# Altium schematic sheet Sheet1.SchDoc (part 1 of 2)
size A0
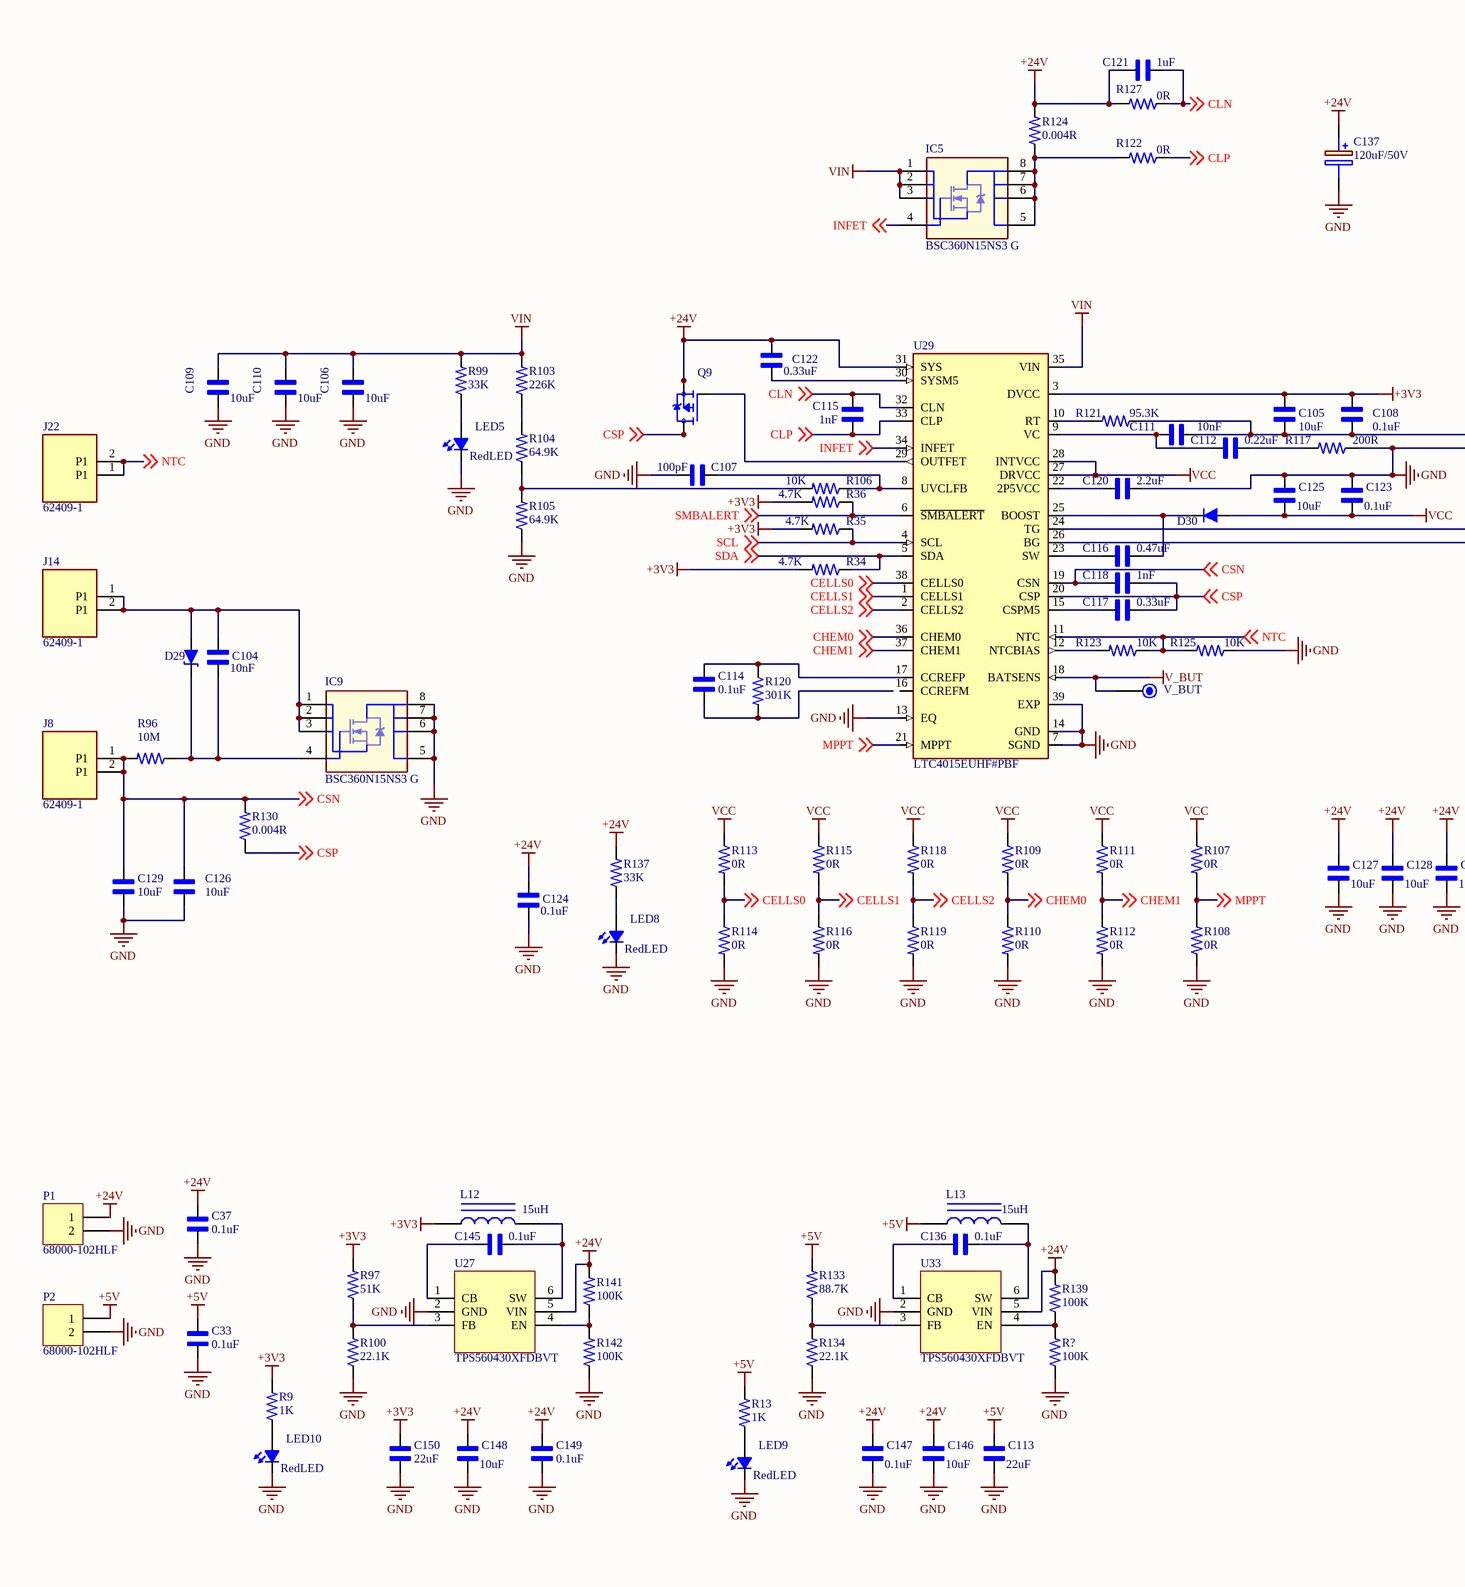
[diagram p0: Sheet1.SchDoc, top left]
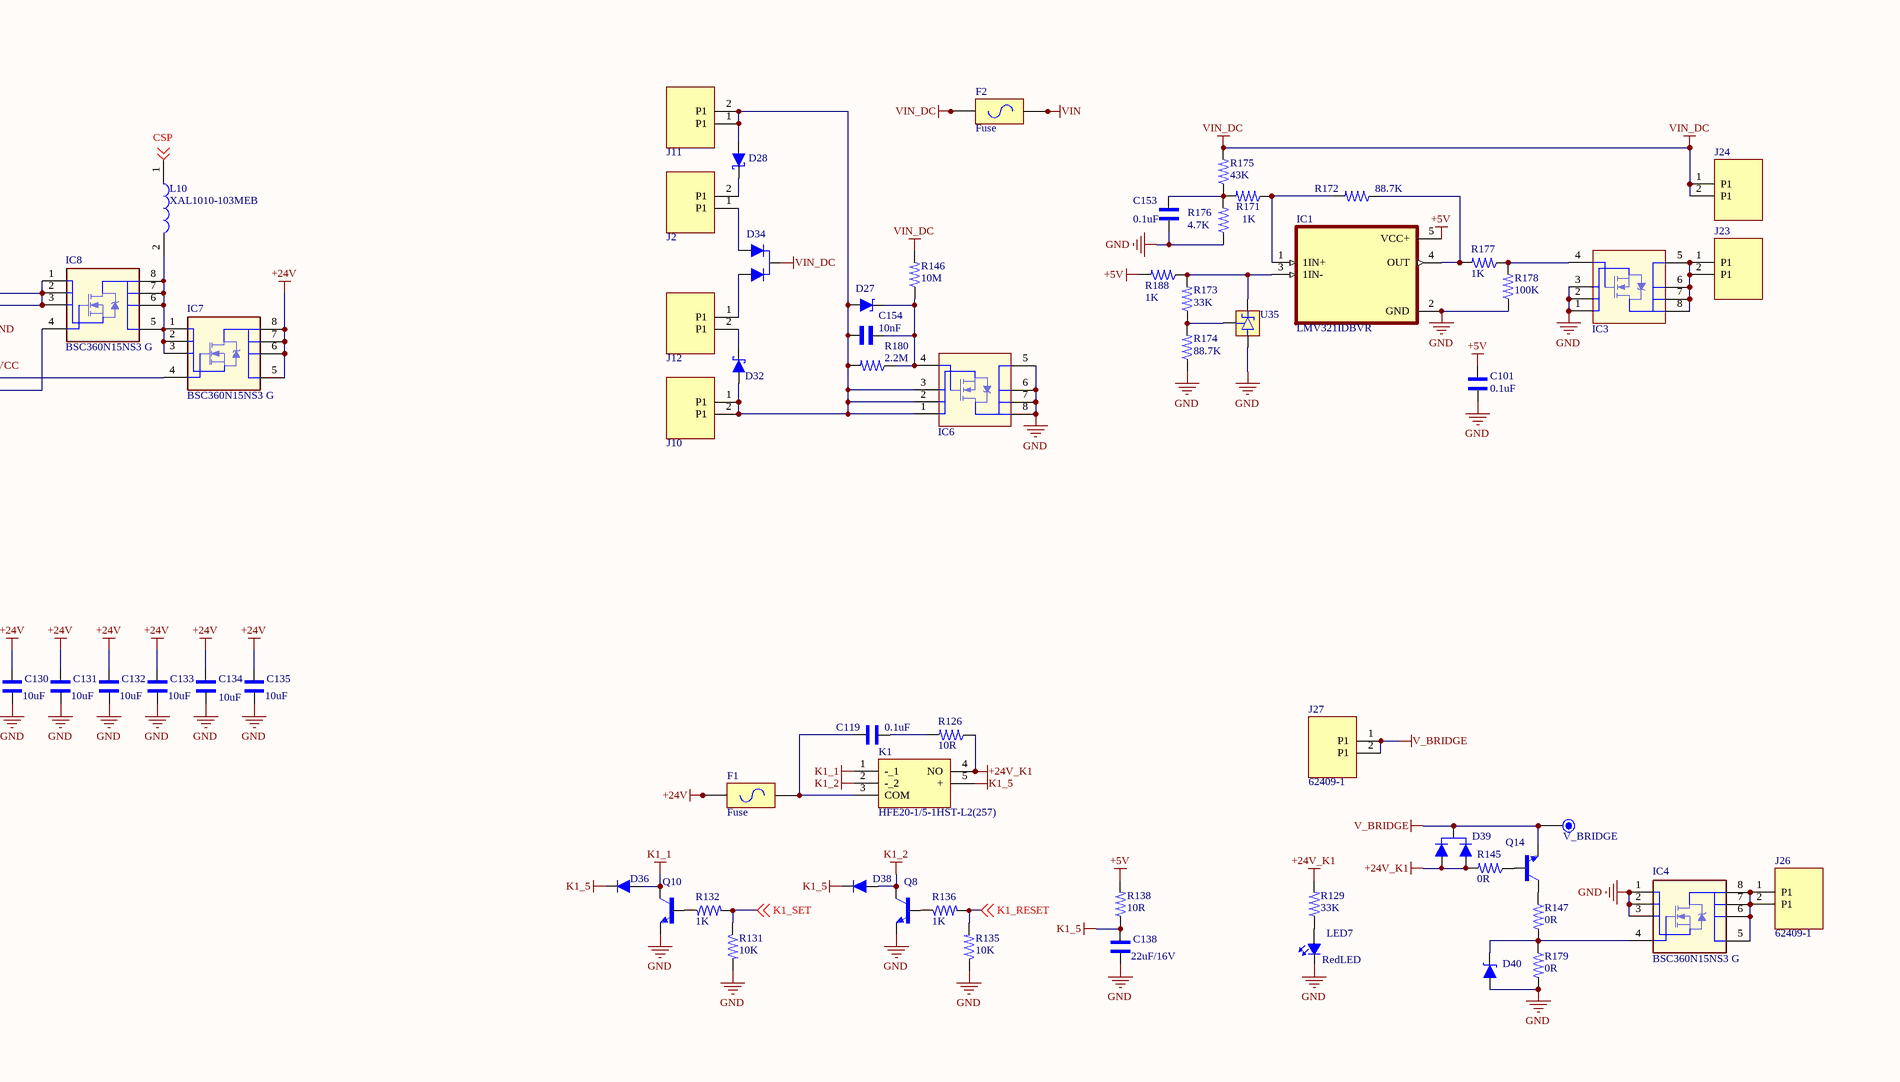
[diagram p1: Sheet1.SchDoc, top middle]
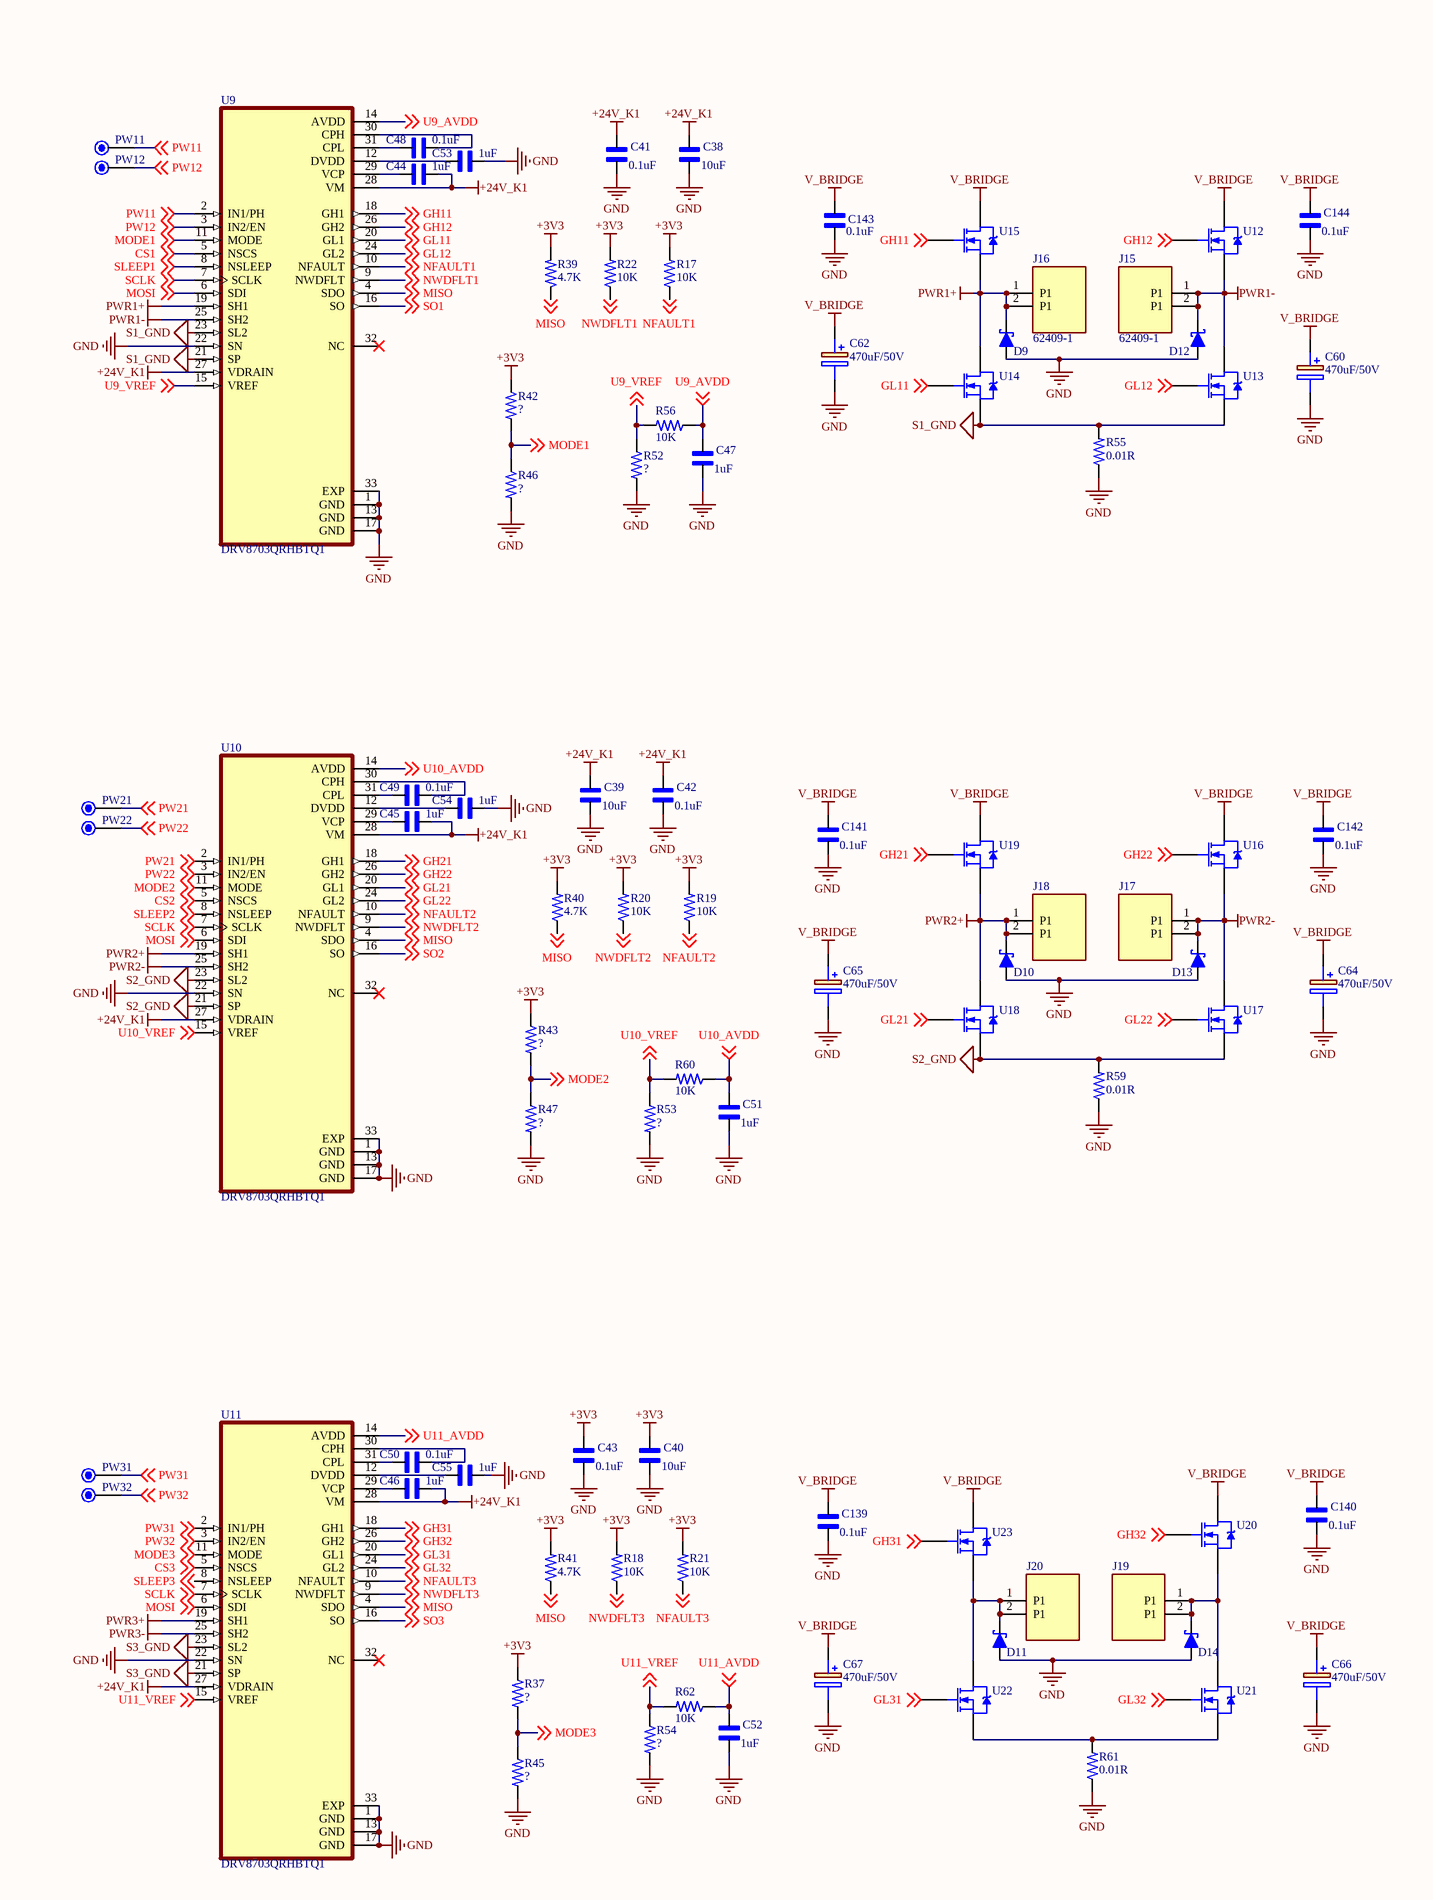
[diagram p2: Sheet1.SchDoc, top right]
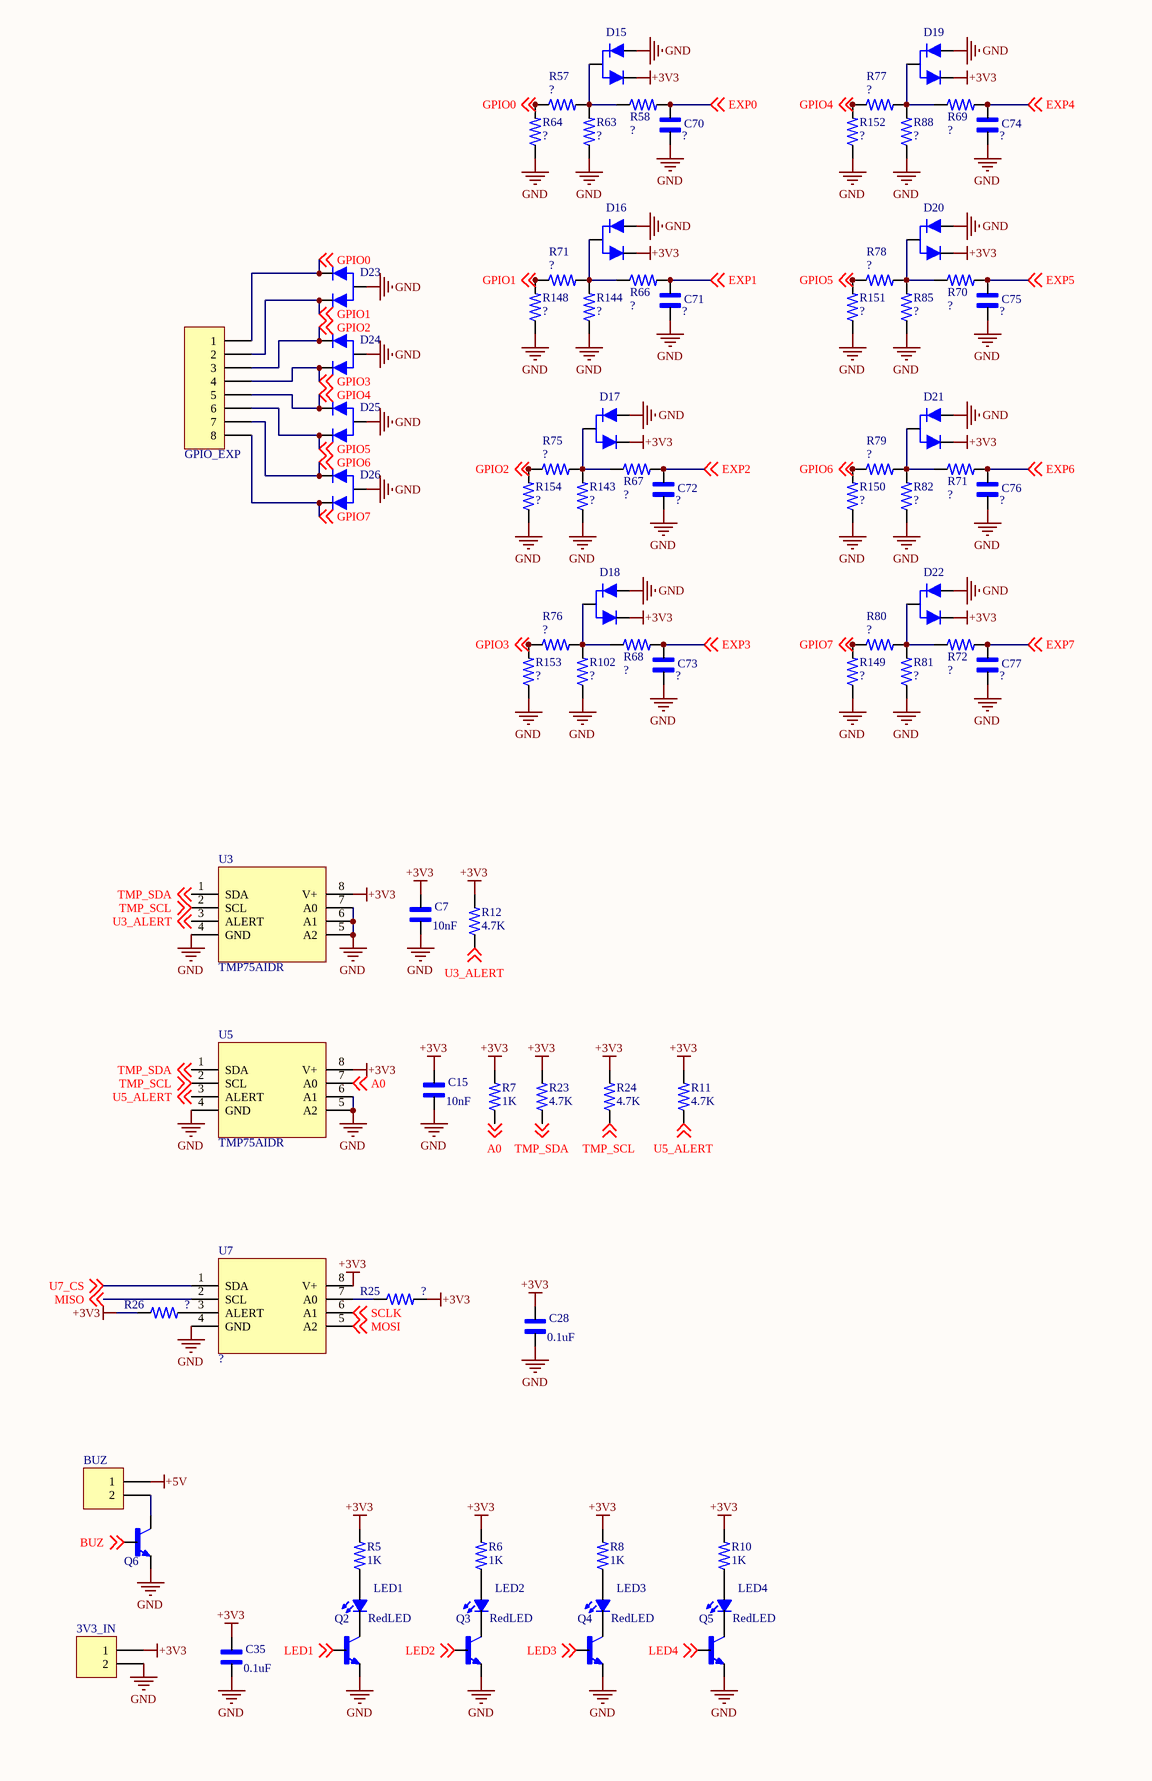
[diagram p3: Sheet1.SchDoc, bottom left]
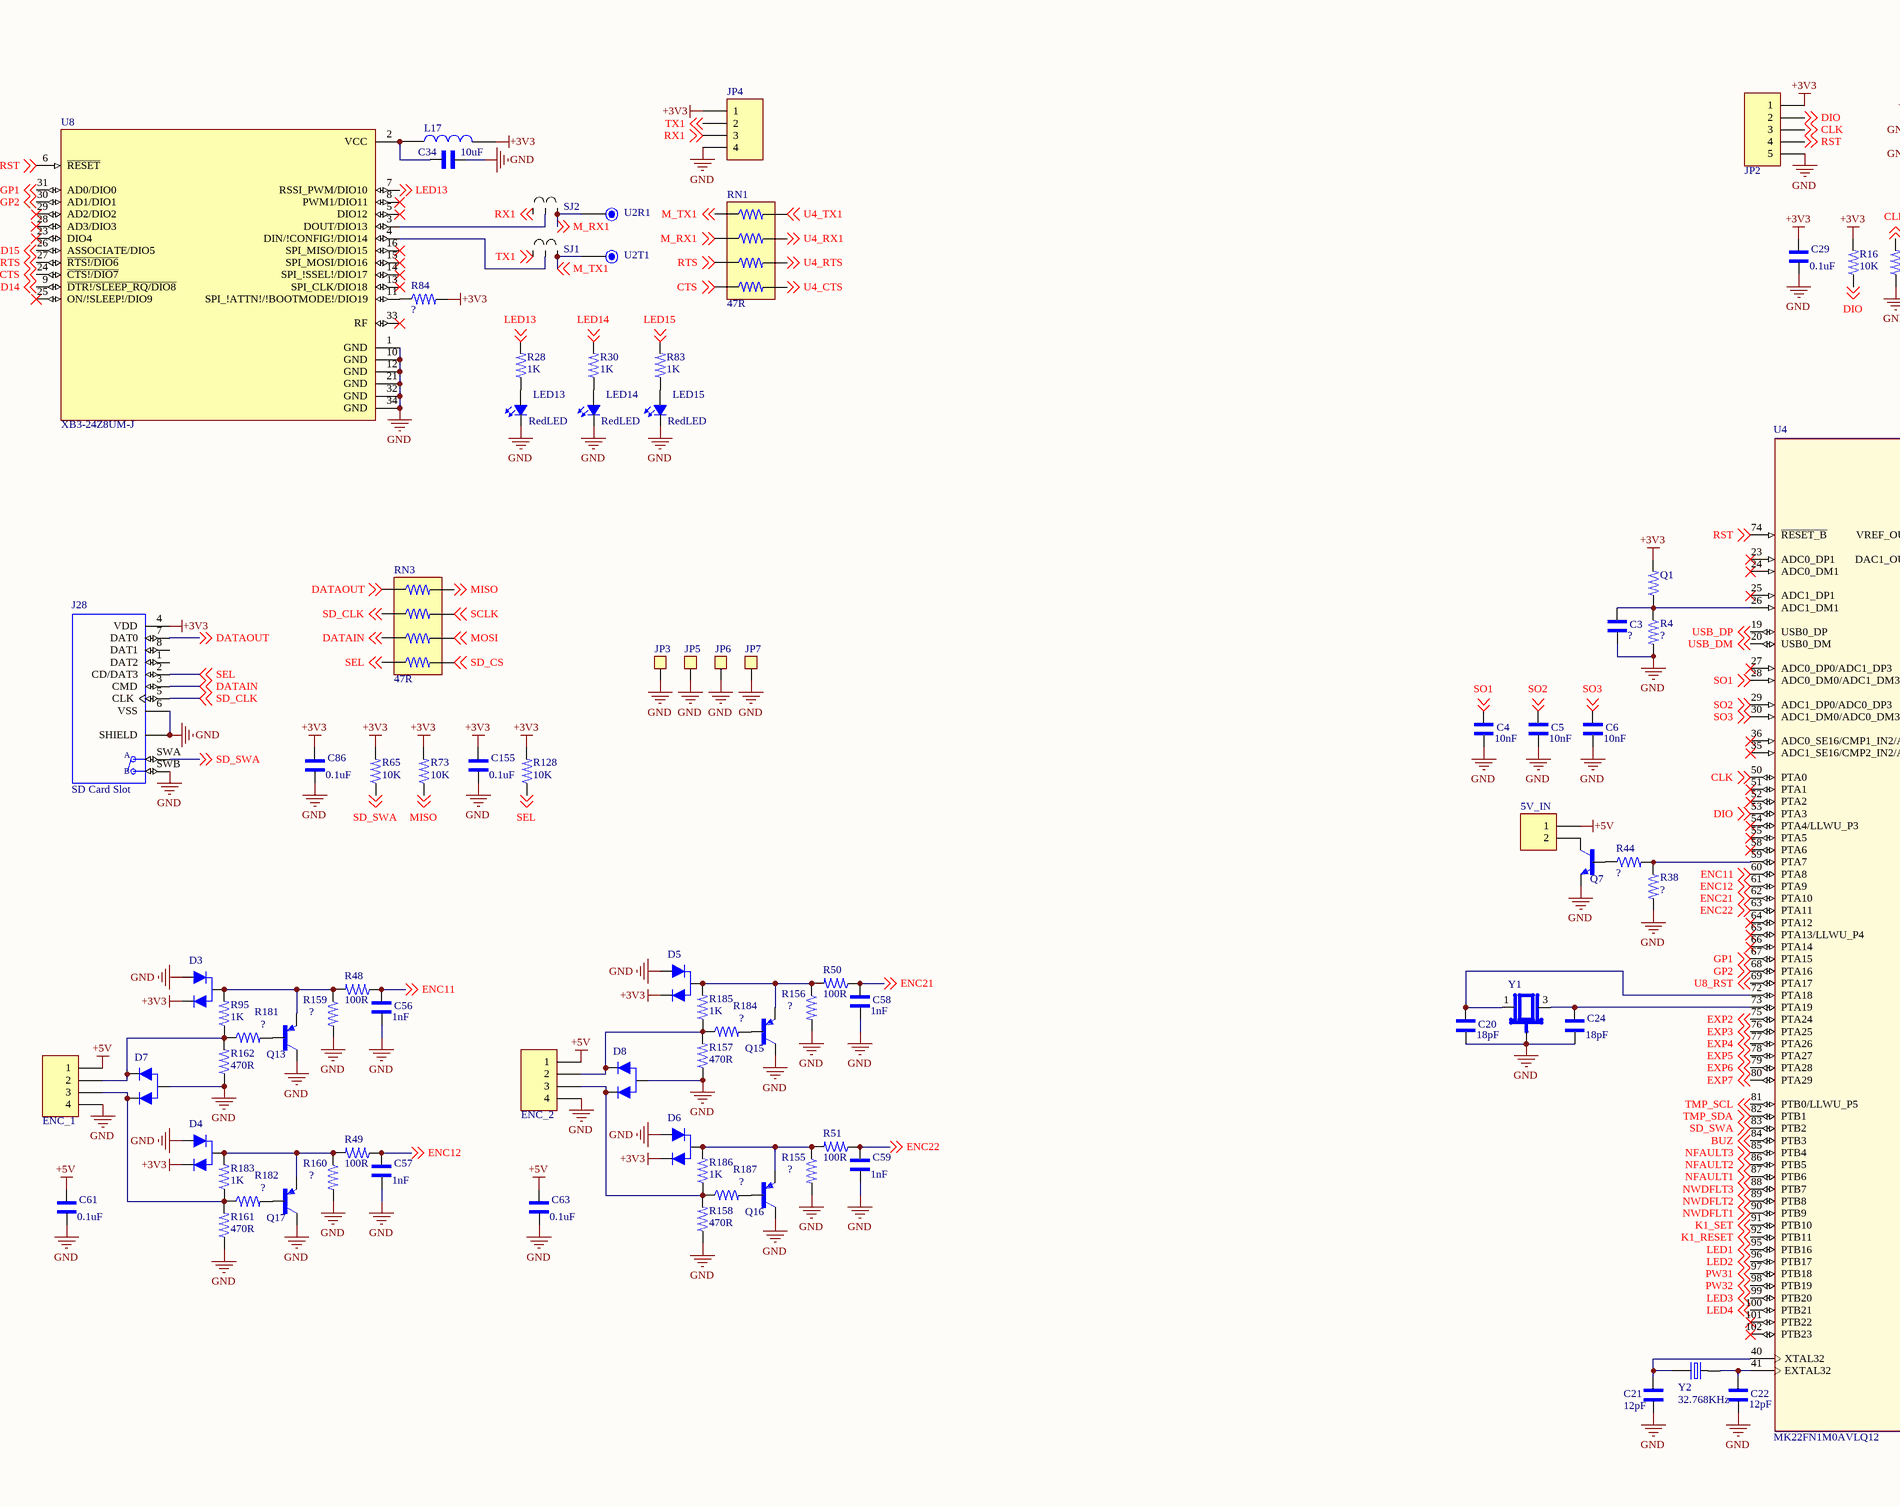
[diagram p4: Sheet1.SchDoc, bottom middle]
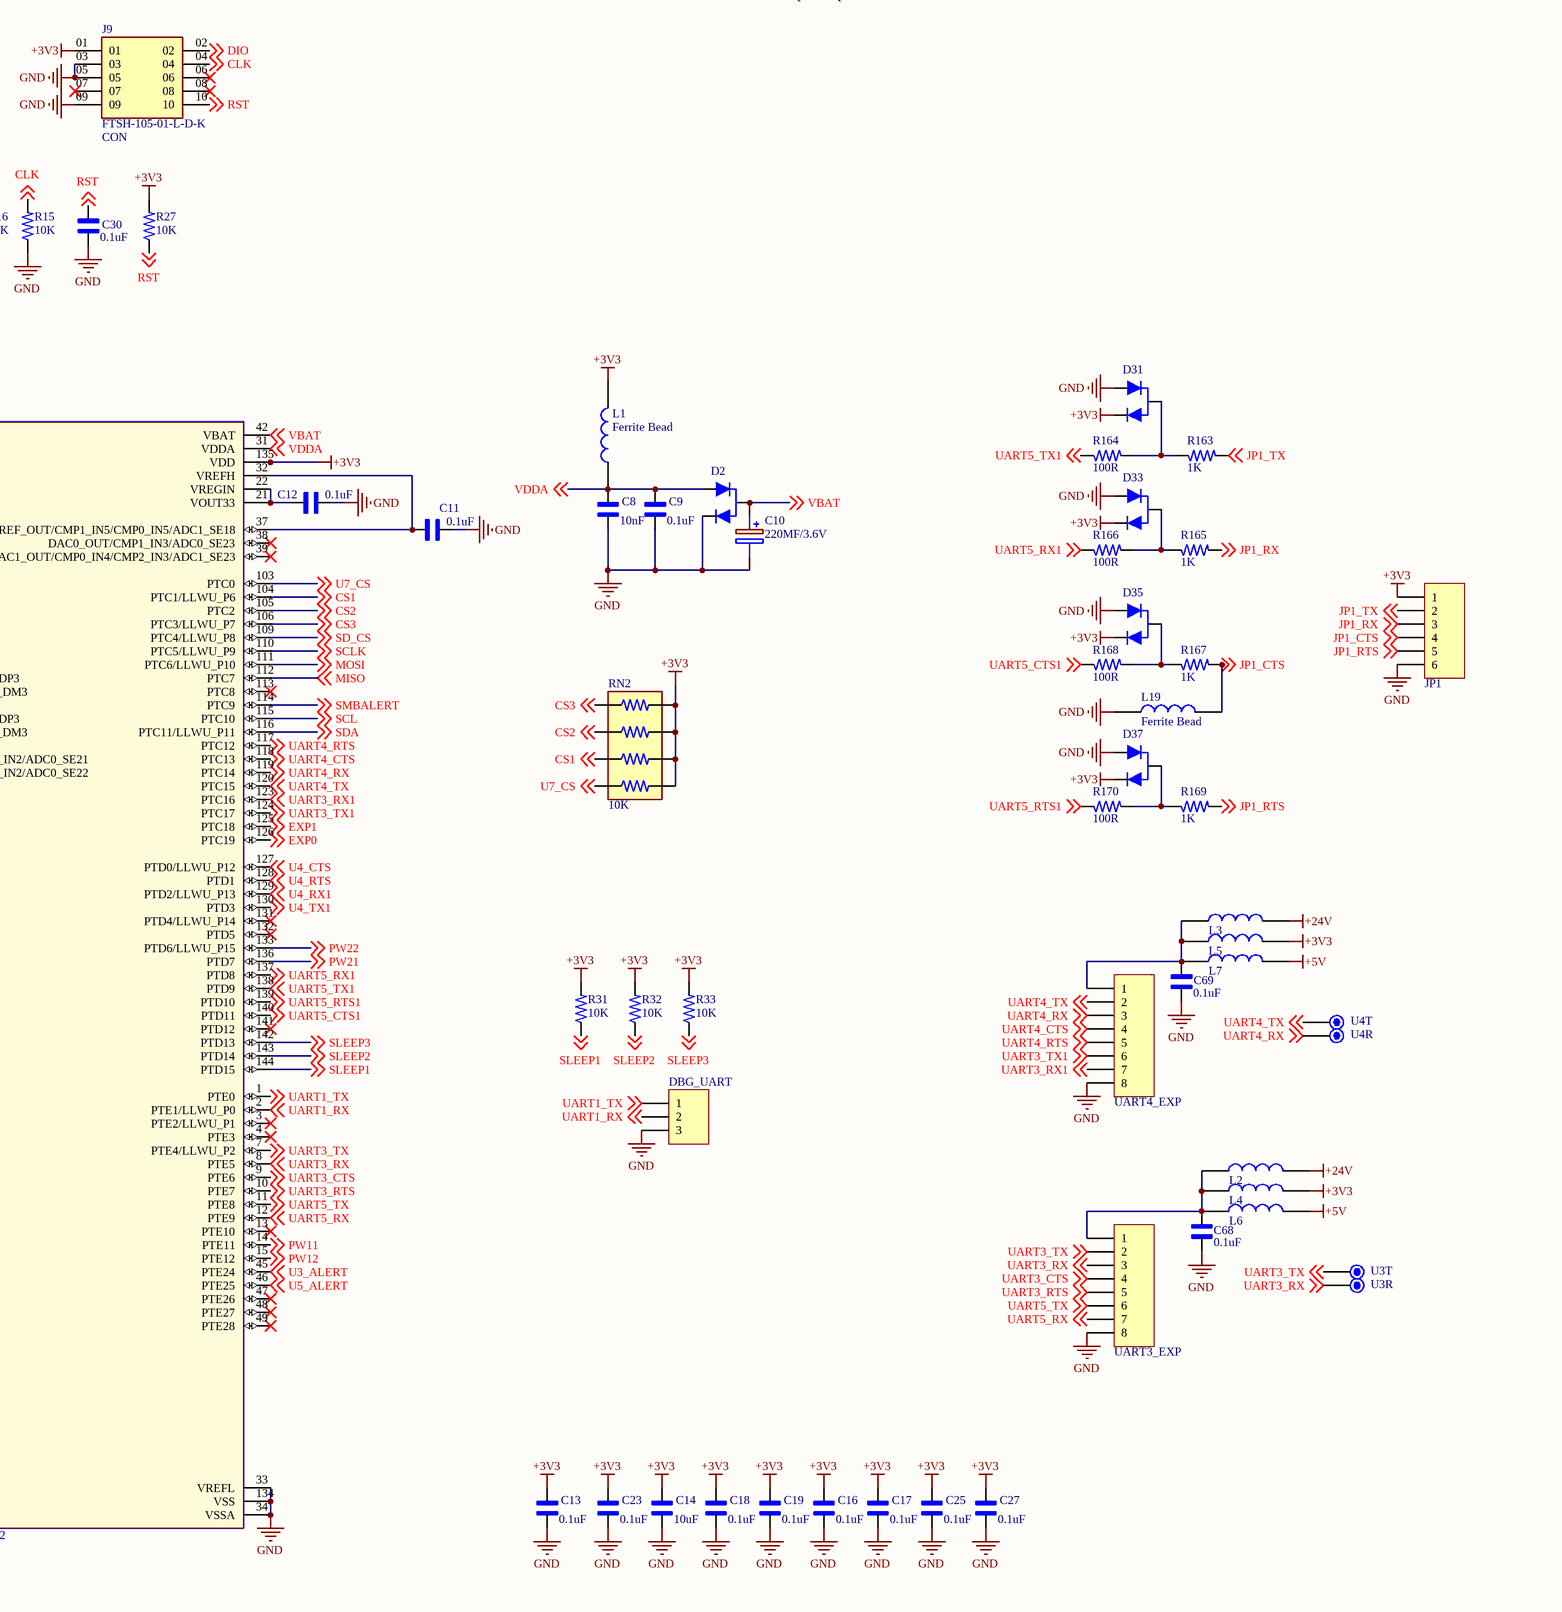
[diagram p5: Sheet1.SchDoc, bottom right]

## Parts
(Parts that share a designator on the sheet are numbered #1, #2 ... from top to bottom, then left to right.)
3V3_IN  68000-102HLF  [HDR1X2(male)]  (value not drawn)
5V_IN  68000-102HLF  [HDR1X2(male)]  (value not drawn)
BUZ  68000-102HLF  [HDR1X2(male)]  (value not drawn)
C3  C?  [CAPC_0805 (2012X140N)]  (value not drawn)
C4  value 10nF  [CAPC_0805 (2012X140N)]  (hidden comment: 08055C103KAT2A)
C5  value 10nF  [CAPC_0805 (2012X140N)]  (hidden comment: 08055C103KAT2A)
C6  value 10nF  [CAPC_0805 (2012X140N)]  (hidden comment: 08055C103KAT2A)
C7  value 10nF  [CAPC_0805 (2012X140N)]  (hidden comment: 08055C103KAT2A)
C8  value 10nF  [CAPC_0805 (2012X140N)]  (hidden comment: 08055C103KAT2A)
C9  value 0.1uF  [CAPC_0805 (2012X140N)]  (hidden comment: 0805B104K500CT)
C10  value 220MF/3.6V  [EEC-RG0V224H]  (hidden comment: EEC-RG0V224H)
C11  value 0.1uF  [CAPC_0805 (2012X140N)]  (hidden comment: 0805B104K500CT)
C12  value 0.1uF  [CAPC_0805 (2012X140N)]  (hidden comment: 0805B104K500CT)
C13  value 0.1uF  [CAPC_0805 (2012X140N)]  (hidden comment: 0805B104K500CT)
C14  value 10uF  [CAPC_0805 (2012X140N)]  (hidden comment: GRM21BR61E106KA73L)
C15  value 10nF  [CAPC_0805 (2012X140N)]  (hidden comment: 08055C103KAT2A)
C16  value 0.1uF  [CAPC_0805 (2012X140N)]  (hidden comment: 0805B104K500CT)
C17  value 0.1uF  [CAPC_0805 (2012X140N)]  (hidden comment: 0805B104K500CT)
C18  value 0.1uF  [CAPC_0805 (2012X140N)]  (hidden comment: 0805B104K500CT)
C19  value 0.1uF  [CAPC_0805 (2012X140N)]  (hidden comment: 0805B104K500CT)
C20  value 18pF  [CAPC_0805 (2012X140N)]  (hidden comment: 0805N180J500CT)
C21  value 12pF  [CAPC_0805 (2012X140N)]  (hidden comment: 0805N120J500CT)
C22  value 12pF  [CAPC_0805 (2012X140N)]  (hidden comment: 0805N120J500CT)
C23  value 0.1uF  [CAPC_0805 (2012X140N)]  (hidden comment: 0805B104K500CT)
C24  value 18pF  [CAPC_0805 (2012X140N)]  (hidden comment: 0805N180J500CT)
C25  value 0.1uF  [CAPC_0805 (2012X140N)]  (hidden comment: 0805B104K500CT)
C27  value 0.1uF  [CAPC_0805 (2012X140N)]  (hidden comment: 0805B104K500CT)
C28  value 0.1uF  [CAPC_0805 (2012X140N)]  (hidden comment: 0805B104K500CT)
C29  value 0.1uF  [CAPC_0805 (2012X140N)]  (hidden comment: 0805B104K500CT)
C30  value 0.1uF  [CAPC_0805 (2012X140N)]  (hidden comment: 0805B104K500CT)
C33  value 0.1uF  [CAPC_0805 (2012X140N)]  (hidden comment: 0805B104K500CT)
C34  value 10uF  [CAPC_0805 (2012X140N)]  (hidden comment: GRM21BR61E106KA73L)
C35  value 0.1uF  [CAPC_0805 (2012X140N)]  (hidden comment: 0805B104K500CT)
C37  value 0.1uF  [CAPC_0805 (2012X140N)]  (hidden comment: 0805B104K500CT)
C38  value 10uF  [CAPC_1210 (3225X280)]  (hidden comment: GRM32ER71H106KA12L)
C39  value 10uF  [CAPC_1210 (3225X280)]  (hidden comment: GRM32ER71H106KA12L)
C40  value 10uF  [CAPC_1210 (3225X280)]  (hidden comment: GRM32ER71H106KA12L)
C41  value 0.1uF  [CAPC_0805 (2012X140N)]  (hidden comment: 0805B104K500CT)
C42  value 0.1uF  [CAPC_0805 (2012X140N)]  (hidden comment: 0805B104K500CT)
C43  value 0.1uF  [CAPC_0805 (2012X140N)]  (hidden comment: 0805B104K500CT)
C44  value 1uF  [CAPC_0805 (2012X140N)]  (hidden comment: 08055C105KAT2A)
C45  value 1uF  [CAPC_0805 (2012X140N)]  (hidden comment: 08055C105KAT2A)
C46  value 1uF  [CAPC_0805 (2012X140N)]  (hidden comment: 08055C105KAT2A)
C47  value 1uF  [CAPC_0805 (2012X140N)]  (hidden comment: 08055C105KAT2A)
C48  value 0.1uF  [CAPC_0805 (2012X140N)]  (hidden comment: 0805B104K500CT)
C49  value 0.1uF  [CAPC_0805 (2012X140N)]  (hidden comment: 0805B104K500CT)
C50  value 0.1uF  [CAPC_0805 (2012X140N)]  (hidden comment: 0805B104K500CT)
C51  value 1uF  [CAPC_0805 (2012X140N)]  (hidden comment: 08055C105KAT2A)
C52  value 1uF  [CAPC_0805 (2012X140N)]  (hidden comment: 08055C105KAT2A)
C53  value 1uF  [CAPC_0805 (2012X140N)]  (hidden comment: 08055C105KAT2A)
C54  value 1uF  [CAPC_0805 (2012X140N)]  (hidden comment: 08055C105KAT2A)
C55  value 1uF  [CAPC_0805 (2012X140N)]  (hidden comment: 08055C105KAT2A)
C56  value 1nF  [CAPC_0805 (2012X140N)]  (hidden comment: 08055C102KAT4A)
C57  value 1nF  [CAPC_0805 (2012X140N)]  (hidden comment: 08055C102KAT4A)
C58  value 1nF  [CAPC_0805 (2012X140N)]  (hidden comment: 08055C102KAT4A)
C59  value 1nF  [CAPC_0805 (2012X140N)]  (hidden comment: 08055C102KAT4A)
C60  value 470uF/50V  [CAPPRD(5x10)]  (hidden comment: ESH477M050AH4AA)
C61  value 0.1uF  [CAPC_0805 (2012X140N)]  (hidden comment: 0805B104K500CT)
C62  value 470uF/50V  [CAPPRD(5x10)]  (hidden comment: ESH477M050AH4AA)
C63  value 0.1uF  [CAPC_0805 (2012X140N)]  (hidden comment: 0805B104K500CT)
C64  value 470uF/50V  [CAPPRD(5x10)]  (hidden comment: ESH477M050AH4AA)
C65  value 470uF/50V  [CAPPRD(5x10)]  (hidden comment: ESH477M050AH4AA)
C66  value 470uF/50V  [CAPPRD(5x10)]  (hidden comment: ESH477M050AH4AA)
C67  value 470uF/50V  [CAPPRD(5x10)]  (hidden comment: ESH477M050AH4AA)
C68  value 0.1uF  [CAPC_0805 (2012X140N)]  (hidden comment: 0805B104K500CT)
C69  value 0.1uF  [CAPC_0805 (2012X140N)]  (hidden comment: 0805B104K500CT)
C70  C?  [CAPC_0805 (2012X140N)]  (value not drawn)
C71  C?  [CAPC_0805 (2012X140N)]  (value not drawn)
C72  C?  [CAPC_0805 (2012X140N)]  (value not drawn)
C73  C?  [CAPC_0805 (2012X140N)]  (value not drawn)
C74  C?  [CAPC_0805 (2012X140N)]  (value not drawn)
C75  C?  [CAPC_0805 (2012X140N)]  (value not drawn)
C76  C?  [CAPC_0805 (2012X140N)]  (value not drawn)
C77  C?  [CAPC_0805 (2012X140N)]  (value not drawn)
C86  value 0.1uF  [CAPC_0805 (2012X140N)]  (hidden comment: 0805B104K500CT)
C101  value 0.1uF  [CAPC_0805 (2012X140N)]  (hidden comment: 0805B104K500CT)
C104  value 10nF  [CAPC_0805 (2012X140N)]  (hidden comment: 08055C103KAT2A)
C105  value 10uF  [CAPC_0805 (2012X140N)]  (hidden comment: GRM21BR61E106KA73L)
C106  value 10uF  [CAPC_1210 (3225X280)]  (hidden comment: GRM32ER71H106KA12L)
C107  value 100pF  [CAPC_0805 (2012X140N)]  (hidden comment: VJ0805A101JXAAC)
C108  value 0.1uF  [CAPC_0805 (2012X140N)]  (hidden comment: 0805B104K500CT)
C109  value 10uF  [CAPC_1210 (3225X280)]  (hidden comment: GRM32ER71H106KA12L)
C110  value 10uF  [CAPC_1210 (3225X280)]  (hidden comment: GRM32ER71H106KA12L)
C111  value 10nF  [CAPC_0805 (2012X140N)]  (hidden comment: 08055C103KAT2A)
C112  value 0.22uF  [CAPC_0805 (2012X140N)]  (hidden comment: UMK212B7224KG-T)
C113  value 22uF  [CAPC_0805 (2012X140N)]  (hidden comment: GRM21BR60J226ME39L)
C114  value 0.1uF  [CAPC_0805 (2012X140N)]  (hidden comment: 0805B104K500CT)
C115  value 1nF  [CAPC_0805 (2012X140N)]  (hidden comment: 08055C102KAT4A)
C116  value 0.47uF  [CAPC_0805 (2012X140N)]  (hidden comment: CC0805ZRY5V9BB474)
C117  value 0.33uF  [CAPC_0805 (2012X140N)]  (hidden comment: VJ0805V334MXACW1BC)
C118  value 1nF  [CAPC_0805 (2012X140N)]  (hidden comment: 08055C102KAT4A)
C119  value 0.1uF  [CAP_1206 (C3216X88N)]  (hidden comment: C1206C104M5RACTU)
C120  value 2.2uF  [CAPC_0805 (2012X140N)]  (hidden comment: UMK212BB7225KG-T)
C121  value 1uF  [CAPC_0805 (2012X140N)]  (hidden comment: 08055C105KAT2A)
C122  value 0.33uF  [CAPC_0805 (2012X140N)]  (hidden comment: VJ0805V334MXACW1BC)
C123  value 0.1uF  [CAPC_0805 (2012X140N)]  (hidden comment: 0805B104K500CT)
C124  value 0.1uF  [CAPC_0805 (2012X140N)]  (hidden comment: 0805B104K500CT)
C125  value 10uF  [CAPC_0805 (2012X140N)]  (hidden comment: GRM21BR61E106KA73L)
C126  value 10uF  [CAPC_1210 (3225X280)]  (hidden comment: GRM32ER71H106KA12L)
C127  value 10uF  [CAPC_1210 (3225X280)]  (hidden comment: GRM32ER71H106KA12L)
C128  value 10uF  [CAPC_1210 (3225X280)]  (hidden comment: GRM32ER71H106KA12L)
C129  value 10uF  [CAPC_1210 (3225X280)]  (hidden comment: GRM32ER71H106KA12L)
C130  value 10uF  [CAPC_1210 (3225X280)]  (hidden comment: GRM32ER71H106KA12L)
C131  value 10uF  [CAPC_1210 (3225X280)]  (hidden comment: GRM32ER71H106KA12L)
C132  value 10uF  [CAPC_1210 (3225X280)]  (hidden comment: GRM32ER71H106KA12L)
C133  value 10uF  [CAPC_1210 (3225X280)]  (hidden comment: GRM32ER71H106KA12L)
C134  value 10uF  [CAPC_1210 (3225X280)]  (hidden comment: GRM32ER71H106KA12L)
C135  value 10uF  [CAPC_1210 (3225X280)]  (hidden comment: GRM32ER71H106KA12L)
C136  value 0.1uF  [CAPC_0805 (2012X140N)]  (hidden comment: 0805B104K500CT)
C137  value 120uF/50V  [CAPPRD(5x10)]  (hidden comment: 860020675017)
C138  value 22uF/16V  [CAP_1206 (C3216X88N)]  (hidden comment: 1206X226K160CT)
C139  value 0.1uF  [CAPC_0805 (2012X140N)]  (hidden comment: 0805B104K500CT)
C140  value 0.1uF  [CAPC_0805 (2012X140N)]  (hidden comment: 0805B104K500CT)
C141  value 0.1uF  [CAPC_0805 (2012X140N)]  (hidden comment: 0805B104K500CT)
C142  value 0.1uF  [CAPC_0805 (2012X140N)]  (hidden comment: 0805B104K500CT)
C143  value 0.1uF  [CAPC_0805 (2012X140N)]  (hidden comment: 0805B104K500CT)
C144  value 0.1uF  [CAPC_0805 (2012X140N)]  (hidden comment: 0805B104K500CT)
C145  value 0.1uF  [CAPC_0805 (2012X140N)]  (hidden comment: 0805B104K500CT)
C146  value 10uF  [CAPC_1210 (3225X280)]  (hidden comment: GRM32ER71H106KA12L)
C147  value 0.1uF  [CAPC_0805 (2012X140N)]  (hidden comment: 0805B104K500CT)
C148  value 10uF  [CAPC_1210 (3225X280)]  (hidden comment: GRM32ER71H106KA12L)
C149  value 0.1uF  [CAPC_0805 (2012X140N)]  (hidden comment: 0805B104K500CT)
C150  value 22uF  [CAPC_0805 (2012X140N)]  (hidden comment: GRM21BR60J226ME39L)
C153  value 0.1uF  [CAPC_0805 (2012X140N)]  (hidden comment: 0805B104K500CT)
C154  value 10nF  [CAPC_0805 (2012X140N)]  (hidden comment: 08055C103KAT2A)
C155  value 0.1uF  [CAPC_0805 (2012X140N)]  (hidden comment: 0805B104K500CT)
D2  BAS40-04E6327  [SOT-23-3(TO-236)]  (value not drawn)
D3  BAT54S,215  [SOT-23-3(TO-236)]  (value not drawn)
D4  BAT54S,215  [SOT-23-3(TO-236)]  (value not drawn)
D5  BAT54S,215  [SOT-23-3(TO-236)]  (value not drawn)
D6  BAT54S,215  [SOT-23-3(TO-236)]  (value not drawn)
D7  BAS40-06  [SOT-23-3(TO-236)]  (value not drawn)
D8  BAS40-06  [SOT-23-3(TO-236)]  (value not drawn)
D9  SMLJ43CA  [DO-214]  (value not drawn)
D10  SMLJ43CA  [DO-214]  (value not drawn)
D11  SMLJ43CA  [DO-214]  (value not drawn)
D12  SMLJ43CA  [DO-214]  (value not drawn)
D13  SMLJ43CA  [DO-214]  (value not drawn)
D14  SMLJ43CA  [DO-214]  (value not drawn)
D15  BAT54S,215  [SOT-23-3(TO-236)]  (value not drawn)
D16  BAT54S,215  [SOT-23-3(TO-236)]  (value not drawn)
D17  BAT54S,215  [SOT-23-3(TO-236)]  (value not drawn)
D18  BAT54S,215  [SOT-23-3(TO-236)]  (value not drawn)
D19  BAT54S,215  [SOT-23-3(TO-236)]  (value not drawn)
D20  BAT54S,215  [SOT-23-3(TO-236)]  (value not drawn)
D21  BAT54S,215  [SOT-23-3(TO-236)]  (value not drawn)
D22  BAT54S,215  [SOT-23-3(TO-236)]  (value not drawn)
D23  BAS40-06  [SOT-23-3(TO-236)]  (value not drawn)
D24  BAS40-06  [SOT-23-3(TO-236)]  (value not drawn)
D25  BAS40-06  [SOT-23-3(TO-236)]  (value not drawn)
D26  BAS40-06  [SOT-23-3(TO-236)]  (value not drawn)
D27  BZX384-B15,115  [SOD323 (SOD2513X114N)]  (value not drawn)
D28  SMAJ43A-E3/61  [DO-214]  (value not drawn)
D29  BZX384-B15,115  [SOD323 (SOD2513X114N)]  (value not drawn)
D30  1N4148WS-7-F  [SOD323 (SOD2513X114N)]  (value not drawn)
D31  BAT54S,215  [SOT-23-3(TO-236)]  (value not drawn)
D32  SMAJ43A-E3/61  [DO-214]  (value not drawn)
D33  BAT54S,215  [SOT-23-3(TO-236)]  (value not drawn)
D34  MBRD20100CT-13  [TO-252AA(DPAK229P990X238-3N)]  (value not drawn)
D35  BAT54S,215  [SOT-23-3(TO-236)]  (value not drawn)
D36  1N4148WS-7-F  [SOD323 (SOD2513X114N)]  (value not drawn)
D37  BAT54S,215  [SOT-23-3(TO-236)]  (value not drawn)
D38  1N4148WS-7-F  [SOD323 (SOD2513X114N)]  (value not drawn)
D39  MBRD20100CT-13  [TO-252AA(DPAK229P990X238-3N)]  (value not drawn)
D40  BZX384-B15,115  [SOD323 (SOD2513X114N)]  (value not drawn)
DBG_UART  68000-103HLF  [HDR1X3 (male)]  (value not drawn)
ENC_1  68000-104HLF  [HDR1X4(male)]  (value not drawn)
ENC_2  68000-104HLF  [HDR1X4(male)]  (value not drawn)
F1  value Fuse  [FUSE Holder]  (hidden comment: C3130)
F2  value Fuse  [FUSE Holder]  (hidden comment: C3130)
GPIO_EXP  68001-108HLF  [HDR1X8 (male)]  (value not drawn)
IC1  LMV321IDBVR  [SOT23-5 (95P284X120-5N)]
IC3  BSC360N15NS3 G  [TRANS_BSC022N04LS6ATMA1]  (value not drawn)
IC4  BSC360N15NS3 G  [TRANS_BSC022N04LS6ATMA1]
IC5  BSC360N15NS3 G  [TRANS_BSC022N04LS6ATMA1]
IC6  BSC360N15NS3 G  [TRANS_BSC022N04LS6ATMA1]  (value not drawn)
IC7  BSC360N15NS3 G  [TRANS_BSC022N04LS6ATMA1]
IC8  BSC360N15NS3 G  [TRANS_BSC022N04LS6ATMA1]
IC9  BSC360N15NS3 G  [TRANS_BSC022N04LS6ATMA1]
J2  62409-1  [TE_62409-1]  (value not drawn)
J8  62409-1  [TE_62409-1]
J9  FTSH-105-01-L-D-K  value CON  [FTSH-105-01-L-D-K]
J10  62409-1  [TE_62409-1]  (value not drawn)
J11  62409-1  [TE_62409-1]  (value not drawn)
J12  62409-1  [TE_62409-1]  (value not drawn)
J14  62409-1  [TE_62409-1]
J15  62409-1  [TE_62409-1]
J16  62409-1  [TE_62409-1]
J17  62409-1  [TE_62409-1]  (value not drawn)
J18  62409-1  [TE_62409-1]  (value not drawn)
J19  62409-1  [TE_62409-1]  (value not drawn)
J20  62409-1  [TE_62409-1]  (value not drawn)
J22  62409-1  [TE_62409-1]
J23  62409-1  [TE_62409-1]  (value not drawn)
J24  62409-1  [TE_62409-1]  (value not drawn)
J26  62409-1  [TE_62409-1]
J27  62409-1  [TE_62409-1]
J28  value SD Card Slot  [HRS_DM3AT-SF-PEJM5]  (hidden comment: DM3AT-SF-PEJM5)
JP1  68000-106HLF  [HDR1X6(male)]  (value not drawn)
JP2  68000-105HLF  [HDR1X5(male)]  (value not drawn)
JP3  PH1-01-UA  [HDR1(male)]  (value not drawn)
JP4  68000-104HLF  [HDR1X4(male)]  (value not drawn)
JP5  PH1-01-UA  [HDR1(male)]  (value not drawn)
JP6  PH1-01-UA  [HDR1(male)]  (value not drawn)
JP7  PH1-01-UA  [HDR1(male)]  (value not drawn)
K1  HFE20-1/5-1HST-L2(257)  [HFE20151HSTL2257]
L1  value Ferrite Bead  [RESC_0805 (2012X50N)]  (hidden comment: BK2125HS601-T)
L2  BK2125HS601-T  [RESC_0805 (2012X50N)]  (value not drawn)
L3  BK2125HS601-T  [RESC_0805 (2012X50N)]  (value not drawn)
L4  BK2125HS601-T  [RESC_0805 (2012X50N)]  (value not drawn)
L5  BK2125HS601-T  [RESC_0805 (2012X50N)]  (value not drawn)
L6  BK2125HS601-T  [RESC_0805 (2012X50N)]  (value not drawn)
L7  BK2125HS601-T  [RESC_0805 (2012X50N)]  (value not drawn)
L10  XAL1010-103MEB  [XAL1010103MEB]
L12  value 15uH  [INDPM6965X300N]  (hidden comment: SRN6045-150M)
L13  value 15uH  [INDPM6965X300N]  (hidden comment: SRN6045-150M)
L17  BK2125HS601-T  [RESC_0805 (2012X50N)]  (value not drawn)
L19  value Ferrite Bead  [RESC_0805 (2012X50N)]  (hidden comment: BK2125HS601-T)
LED1  value RedLED  [LED_0805_R]  (hidden comment: EL-17-21SURC/S530-A2/TR8)
LED2  value RedLED  [LED_0805_R]  (hidden comment: EL-17-21SURC/S530-A2/TR8)
LED3  value RedLED  [LED_0805_R]  (hidden comment: EL-17-21SURC/S530-A2/TR8)
LED4  value RedLED  [LED_0805_R]  (hidden comment: EL-17-21SURC/S530-A2/TR8)
LED5  value RedLED  [LED_0805_R]  (hidden comment: EL-17-21SURC/S530-A2/TR8)
LED7  value RedLED  [LED_0805_R]  (hidden comment: EL-17-21SURC/S530-A2/TR8)
LED8  value RedLED  [LED_0805_R]  (hidden comment: EL-17-21SURC/S530-A2/TR8)
LED9  value RedLED  [LED_0805_R]  (hidden comment: EL-17-21SURC/S530-A2/TR8)
LED10  value RedLED  [LED_0805_R]  (hidden comment: EL-17-21SURC/S530-A2/TR8)
LED13  value RedLED  [LED_0805_R]  (hidden comment: EL-17-21SURC/S530-A2/TR8)
LED14  value RedLED  [LED_0805_R]  (hidden comment: EL-17-21SURC/S530-A2/TR8)
LED15  value RedLED  [LED_0805_R]  (hidden comment: EL-17-21SURC/S530-A2/TR8)
P1  68000-102HLF  [HDR1X2(male)]
P2  68000-102HLF  [HDR1X2(male)]
PW11  E_PAD  [E_PAD (SMD)]  (value not drawn)
PW12  E_PAD  [E_PAD (SMD)]  (value not drawn)
PW21  E_PAD  [E_PAD (SMD)]  (value not drawn)
PW22  E_PAD  [E_PAD (SMD)]  (value not drawn)
PW31  E_PAD  [E_PAD (SMD)]  (value not drawn)
PW32  E_PAD  [E_PAD (SMD)]  (value not drawn)
Q1  Q?  [RES (0603)]  (value not drawn)
Q2  PDTC114ET,215  [SOT-23-3(TO-236)]  (value not drawn)
Q3  PDTC114ET,215  [SOT-23-3(TO-236)]  (value not drawn)
Q4  PDTC114ET,215  [SOT-23-3(TO-236)]  (value not drawn)
Q5  PDTC114ET,215  [SOT-23-3(TO-236)]  (value not drawn)
Q6  PDTC114ET,215  [SOT-23-3(TO-236)]  (value not drawn)
Q7  PDTC114ET,215  [SOT-23-3(TO-236)]  (value not drawn)
Q8  BC847B-7-F  [SOT-23-3(TO-236)]  (value not drawn)
Q9  SI7611DN-T1-GE3  [SIS468DN-T1-GE3]  (value not drawn)
Q10  BC847B-7-F  [SOT-23-3(TO-236)]  (value not drawn)
Q13  PNP TRANS  [SOT-23-3(TO-236)]  (value not drawn)
Q14  BC847B-7-F  [SOT-23-3(TO-236)]  (value not drawn)
Q15  PNP TRANS  [SOT-23-3(TO-236)]  (value not drawn)
Q16  PNP TRANS  [SOT-23-3(TO-236)]  (value not drawn)
Q17  PNP TRANS  [SOT-23-3(TO-236)]  (value not drawn)
R4  R?  [RESC_0805 (2012X50N)]  (value not drawn)
R5  value 1K  [RESC_0805 (2012X50N)]  (hidden comment: RC0805FR-071KL)
R6  value 1K  [RESC_0805 (2012X50N)]  (hidden comment: RC0805FR-071KL)
R7  value 1K  [RESC_0805 (2012X50N)]  (hidden comment: RC0805FR-071KL)
R8  value 1K  [RESC_0805 (2012X50N)]  (hidden comment: RC0805FR-071KL)
R9  value 1K  [RESC_0805 (2012X50N)]  (hidden comment: RC0805FR-071KL)
R10  value 1K  [RESC_0805 (2012X50N)]  (hidden comment: RC0805FR-071KL)
R11  value 4.7K  [RESC_0805 (2012X50N)]  (hidden comment: CRCW08054K70FKEA)
R12  value 4.7K  [RESC_0805 (2012X50N)]  (hidden comment: CRCW08054K70FKEA)
R13  value 1K  [RESC_0805 (2012X50N)]  (hidden comment: RC0805FR-071KL)
R15  value 10K  [RESC_0805 (2012X50N)]  (hidden comment: RC0805FR-0710KL)
R16  value 10K  [RESC_0805 (2012X50N)]  (hidden comment: RC0805FR-0710KL)
R17  value 10K  [RESC_0805 (2012X50N)]  (hidden comment: RC0805FR-0710KL)
R18  value 10K  [RESC_0805 (2012X50N)]  (hidden comment: RC0805FR-0710KL)
R19  value 10K  [RESC_0805 (2012X50N)]  (hidden comment: RC0805FR-0710KL)
R20  value 10K  [RESC_0805 (2012X50N)]  (hidden comment: RC0805FR-0710KL)
R21  value 10K  [RESC_0805 (2012X50N)]  (hidden comment: RC0805FR-0710KL)
R22  value 10K  [RESC_0805 (2012X50N)]  (hidden comment: RC0805FR-0710KL)
R23  value 4.7K  [RESC_0805 (2012X50N)]  (hidden comment: CRCW08054K70FKEA)
R24  value 4.7K  [RESC_0805 (2012X50N)]  (hidden comment: CRCW08054K70FKEA)
R25  R?  [RESC_0805 (2012X50N)]  (value not drawn)
R26  R?  [RESC_0805 (2012X50N)]  (value not drawn)
R27  value 10K  [RESC_0805 (2012X50N)]  (hidden comment: RC0805FR-0710KL)
R28  value 1K  [RESC_0805 (2012X50N)]  (hidden comment: RC0805FR-071KL)
R30  value 1K  [RESC_0805 (2012X50N)]  (hidden comment: RC0805FR-071KL)
R31  value 10K  [RESC_0805 (2012X50N)]  (hidden comment: RC0805FR-0710KL)
R32  value 10K  [RESC_0805 (2012X50N)]  (hidden comment: RC0805FR-0710KL)
R33  value 10K  [RESC_0805 (2012X50N)]  (hidden comment: RC0805FR-0710KL)
R34  value 4.7K  [RESC_0805 (2012X50N)]  (hidden comment: CRCW08054K70FKEA)
R35  value 4.7K  [RESC_0805 (2012X50N)]  (hidden comment: CRCW08054K70FKEA)
R36  value 4.7K  [RESC_0805 (2012X50N)]  (hidden comment: CRCW08054K70FKEA)
R37  RC0805FR-070RL  [RESC_0805 (2012X50N)]  (value not drawn)
R38  R?  [RESC_0805 (2012X50N)]  (value not drawn)
R39  value 4.7K  [RESC_0805 (2012X50N)]  (hidden comment: CRCW08054K70FKEA)
R40  value 4.7K  [RESC_0805 (2012X50N)]  (hidden comment: CRCW08054K70FKEA)
R41  value 4.7K  [RESC_0805 (2012X50N)]  (hidden comment: CRCW08054K70FKEA)
R42  RC0805FR-070RL  [RESC_0805 (2012X50N)]  (value not drawn)
R43  RC0805FR-070RL  [RESC_0805 (2012X50N)]  (value not drawn)
R44  R?  [RESC_0805 (2012X50N)]  (value not drawn)
R45  RC0805FR-070RL  [RESC_0805 (2012X50N)]  (value not drawn)
R46  RC0805FR-070RL  [RESC_0805 (2012X50N)]  (value not drawn)
R47  RC0805FR-070RL  [RESC_0805 (2012X50N)]  (value not drawn)
R48  value 100R  [RESC_0805 (2012X50N)]  (hidden comment: WR08X1000FTL)
R49  value 100R  [RESC_0805 (2012X50N)]  (hidden comment: WR08X1000FTL)
R50  value 100R  [RESC_0805 (2012X50N)]  (hidden comment: WR08X1000FTL)
R51  value 100R  [RESC_0805 (2012X50N)]  (hidden comment: WR08X1000FTL)
R52  RC0805FR-070RL  [RESC_0805 (2012X50N)]  (value not drawn)
R53  RC0805FR-070RL  [RESC_0805 (2012X50N)]  (value not drawn)
R54  RC0805FR-070RL  [RESC_0805 (2012X50N)]  (value not drawn)
R55  value 0.01R  [RES_2512 (C6331X88N)]  (hidden comment: CSR2512A0R01F)
R56  value 10K  [RESC_0805 (2012X50N)]  (hidden comment: RC0805FR-0710KL)
R57  R?  [RESC_0805 (2012X50N)]  (value not drawn)
R58  R?  [RESC_0805 (2012X50N)]  (value not drawn)
R59  value 0.01R  [RES_2512 (C6331X88N)]  (hidden comment: CSR2512A0R01F)
R60  value 10K  [RESC_0805 (2012X50N)]  (hidden comment: RC0805FR-0710KL)
R61  value 0.01R  [RES_2512 (C6331X88N)]  (hidden comment: CSR2512A0R01F)
R62  value 10K  [RESC_0805 (2012X50N)]  (hidden comment: RC0805FR-0710KL)
R63  R?  [RESC_0805 (2012X50N)]  (value not drawn)
R64  R?  [RESC_0805 (2012X50N)]  (value not drawn)
R65  value 10K  [RESC_0805 (2012X50N)]  (hidden comment: RC0805FR-0710KL)
R66  R?  [RESC_0805 (2012X50N)]  (value not drawn)
R67  R?  [RESC_0805 (2012X50N)]  (value not drawn)
R68  R?  [RESC_0805 (2012X50N)]  (value not drawn)
R69  R?  [RESC_0805 (2012X50N)]  (value not drawn)
R70  R?  [RESC_0805 (2012X50N)]  (value not drawn)
R71#1  R?  [RESC_0805 (2012X50N)]  (value not drawn)
R71#2  R?  [RESC_0805 (2012X50N)]  (value not drawn)
R72  R?  [RESC_0805 (2012X50N)]  (value not drawn)
R73  value 10K  [RESC_0805 (2012X50N)]  (hidden comment: RC0805FR-0710KL)
R75  R?  [RESC_0805 (2012X50N)]  (value not drawn)
R76  R?  [RESC_0805 (2012X50N)]  (value not drawn)
R77  R?  [RESC_0805 (2012X50N)]  (value not drawn)
R78  R?  [RESC_0805 (2012X50N)]  (value not drawn)
R79  R?  [RESC_0805 (2012X50N)]  (value not drawn)
R80  R?  [RESC_0805 (2012X50N)]  (value not drawn)
R81  R?  [RESC_0805 (2012X50N)]  (value not drawn)
R82  R?  [RESC_0805 (2012X50N)]  (value not drawn)
R83  value 1K  [RESC_0805 (2012X50N)]  (hidden comment: RC0805FR-071KL)
R84  RC0805FR-070RL  [RESC_0805 (2012X50N)]  (value not drawn)
R85  R?  [RESC_0805 (2012X50N)]  (value not drawn)
R88  R?  [RESC_0805 (2012X50N)]  (value not drawn)
R95  value 1K  [RESC_0805 (2012X50N)]  (hidden comment: RC0805FR-071KL)
R96  value 10M  [RESC_0805 (2012X50N)]  (hidden comment: CRCW080510M0FKEA)
R97  value 51K  [RESC_0805 (2012X50N)]  (hidden comment: RC0805FR-0751KL)
R99  value 33K  [RESC_0805 (2012X50N)]  (hidden comment: RC0805FR-0733KL)
R100  value 22.1K  [RESC_0805 (2012X50N)]  (hidden comment: RC0805FR-0722K1L)
R102  R?  [RESC_0805 (2012X50N)]  (value not drawn)
R103  value 226K  [RESC_0805 (2012X50N)]  (hidden comment: RC0805FR-07226KL)
R104  value 64.9K  [RESC_0805 (2012X50N)]  (hidden comment: RC0805FR-0764K9L)
R105  value 64.9K  [RESC_0805 (2012X50N)]  (hidden comment: RC0805FR-0764K9L)
R106  value 10K  [RESC_0805 (2012X50N)]  (hidden comment: RC0805FR-0710KL)
R107  value 0R  [RESC_0805 (2012X50N)]  (hidden comment: RC0805FR-070RL)
R108  value 0R  [RESC_0805 (2012X50N)]  (hidden comment: RC0805FR-070RL)
R109  value 0R  [RESC_0805 (2012X50N)]  (hidden comment: RC0805FR-070RL)
R110  value 0R  [RESC_0805 (2012X50N)]  (hidden comment: RC0805FR-070RL)
R111  value 0R  [RESC_0805 (2012X50N)]  (hidden comment: RC0805FR-070RL)
R112  value 0R  [RESC_0805 (2012X50N)]  (hidden comment: RC0805FR-070RL)
R113  value 0R  [RESC_0805 (2012X50N)]  (hidden comment: RC0805FR-070RL)
R114  value 0R  [RESC_0805 (2012X50N)]  (hidden comment: RC0805FR-070RL)
R115  value 0R  [RESC_0805 (2012X50N)]  (hidden comment: RC0805FR-070RL)
R116  value 0R  [RESC_0805 (2012X50N)]  (hidden comment: RC0805FR-070RL)
R117  value 200R  [RESC_0805 (2012X50N)]  (hidden comment: RC0805FR-07200RL)
R118  value 0R  [RESC_0805 (2012X50N)]  (hidden comment: RC0805FR-070RL)
R119  value 0R  [RESC_0805 (2012X50N)]  (hidden comment: RC0805FR-070RL)
R120  value 301K  [RESC_0805 (2012X50N)]  (hidden comment: RT0805BRD07301KL)
R121  value 95.3K  [RESC_0805 (2012X50N)]  (hidden comment: RC0805FR-0795K3L)
R122  value 0R  [RESC_0805 (2012X50N)]  (hidden comment: RC0805FR-070RL)
R123  value 10K  [RESC_0805 (2012X50N)]  (hidden comment: RC0805FR-0710KL)
R124  value 0.004R  [RES_2512 (C6331X88N)]  (hidden comment: PA2512FKF7W0R004E)
R125  value 10K  [RESC_0805 (2012X50N)]  (hidden comment: RC0805FR-0710KL)
R126  value 10R  [RESC3115X65N]  (hidden comment: RC1206FR-0710RL)
R127  value 0R  [RESC_0805 (2012X50N)]  (hidden comment: RC0805FR-070RL)
R128  value 10K  [RESC_0805 (2012X50N)]  (hidden comment: RC0805FR-0710KL)
R129  value 33K  [RESC_0805 (2012X50N)]  (hidden comment: RC0805FR-0733KL)
R130  value 0.004R  [RES_2512 (C6331X88N)]  (hidden comment: PA2512FKF7W0R004E)
R131  value 10K  [RESC_0805 (2012X50N)]  (hidden comment: RC0805FR-0710KL)
R132  value 1K  [RESC_0805 (2012X50N)]  (hidden comment: RC0805FR-071KL)
R133  value 88.7K  [RESC_0805 (2012X50N)]  (hidden comment: RC0805FR-0788K7L)
R134  value 22.1K  [RESC_0805 (2012X50N)]  (hidden comment: RC0805FR-0722K1L)
R135  value 10K  [RESC_0805 (2012X50N)]  (hidden comment: RC0805FR-0710KL)
R136  value 1K  [RESC_0805 (2012X50N)]  (hidden comment: RC0805FR-071KL)
R137  value 33K  [RESC_0805 (2012X50N)]  (hidden comment: RC0805FR-0733KL)
R138  value 10R  [RESC3115X65N]  (hidden comment: RC1206FR-0710RL)
R139  value 100K  [RESC_0805 (2012X50N)]  (hidden comment: CRCW0805100KFKEA)
R141  value 100K  [RESC_0805 (2012X50N)]  (hidden comment: CRCW0805100KFKEA)
R142  value 100K  [RESC_0805 (2012X50N)]  (hidden comment: CRCW0805100KFKEA)
R143  R?  [RESC_0805 (2012X50N)]  (value not drawn)
R144  R?  [RESC_0805 (2012X50N)]  (value not drawn)
R145  value 0R  [RESC_0805 (2012X50N)]  (hidden comment: RC0805FR-070RL)
R146  value 10M  [RESC_0805 (2012X50N)]  (hidden comment: CRCW080510M0FKEA)
R147  value 0R  [RESC_0805 (2012X50N)]  (hidden comment: RC0805FR-070RL)
R148  R?  [RESC_0805 (2012X50N)]  (value not drawn)
R149  R?  [RESC_0805 (2012X50N)]  (value not drawn)
R150  R?  [RESC_0805 (2012X50N)]  (value not drawn)
R151  R?  [RESC_0805 (2012X50N)]  (value not drawn)
R152  R?  [RESC_0805 (2012X50N)]  (value not drawn)
R153  R?  [RESC_0805 (2012X50N)]  (value not drawn)
R154  R?  [RESC_0805 (2012X50N)]  (value not drawn)
R155  RC0805FR-070RL  [RESC_0805 (2012X50N)]  (value not drawn)
R156  RC0805FR-070RL  [RESC_0805 (2012X50N)]  (value not drawn)
R157  value 470R  [RESC_0805 (2012X50N)]  (hidden comment: CRCW0805470RFKEAC)
R158  value 470R  [RESC_0805 (2012X50N)]  (hidden comment: CRCW0805470RFKEAC)
R159  RC0805FR-070RL  [RESC_0805 (2012X50N)]  (value not drawn)
R160  RC0805FR-070RL  [RESC_0805 (2012X50N)]  (value not drawn)
R161  value 470R  [RESC_0805 (2012X50N)]  (hidden comment: CRCW0805470RFKEAC)
R162  value 470R  [RESC_0805 (2012X50N)]  (hidden comment: CRCW0805470RFKEAC)
R163  value 1K  [RESC_0805 (2012X50N)]  (hidden comment: RC0805FR-071KL)
R164  value 100R  [RESC_0805 (2012X50N)]  (hidden comment: WR08X1000FTL)
R165  value 1K  [RESC_0805 (2012X50N)]  (hidden comment: RC0805FR-071KL)
R166  value 100R  [RESC_0805 (2012X50N)]  (hidden comment: WR08X1000FTL)
R167  value 1K  [RESC_0805 (2012X50N)]  (hidden comment: RC0805FR-071KL)
R168  value 100R  [RESC_0805 (2012X50N)]  (hidden comment: WR08X1000FTL)
R169  value 1K  [RESC_0805 (2012X50N)]  (hidden comment: RC0805FR-071KL)
R170  value 100R  [RESC_0805 (2012X50N)]  (hidden comment: WR08X1000FTL)
R171  value 1K  [RESC_0805 (2012X50N)]  (hidden comment: RC0805FR-071KL)
R172  value 88.7K  [RESC_0805 (2012X50N)]  (hidden comment: RC0805FR-0788K7L)
R173  value 33K  [RESC_0805 (2012X50N)]  (hidden comment: RC0805FR-0733KL)
R174  value 88.7K  [RESC_0805 (2012X50N)]  (hidden comment: RC0805FR-0788K7L)
R175  value 43K  [RESC_0805 (2012X50N)]  (hidden comment: RC0805JR-0743KL)
R176  value 4.7K  [RESC_0805 (2012X50N)]  (hidden comment: CRCW08054K70FKEA)
R177  value 1K  [RESC_0805 (2012X50N)]  (hidden comment: RC0805FR-071KL)
R178  value 100K  [RESC_0805 (2012X50N)]  (hidden comment: CRCW0805100KFKEA)
R179  value 0R  [RESC_0805 (2012X50N)]  (hidden comment: RC0805FR-070RL)
R180  value 2.2M  [RESC_0805 (2012X50N)]  (hidden comment: ERJ-6ENF2204V)
R181  RC0805FR-070RL  [RESC_0805 (2012X50N)]  (value not drawn)
R182  RC0805FR-070RL  [RESC_0805 (2012X50N)]  (value not drawn)
R183  value 1K  [RESC_0805 (2012X50N)]  (hidden comment: RC0805FR-071KL)
R184  RC0805FR-070RL  [RESC_0805 (2012X50N)]  (value not drawn)
R185  value 1K  [RESC_0805 (2012X50N)]  (hidden comment: RC0805FR-071KL)
R186  value 1K  [RESC_0805 (2012X50N)]  (hidden comment: RC0805FR-071KL)
R187  RC0805FR-070RL  [RESC_0805 (2012X50N)]  (value not drawn)
R188  value 1K  [RESC_0805 (2012X50N)]  (hidden comment: RC0805FR-071KL)
R?  value 100K  [RESC_0805 (2012X50N)]  (hidden comment: CRCW0805100KFKEA)
RN1  value 47R  [RESCAV80P320X160X70-8N]  (hidden comment: TC164-JR-0747RL)
RN2  value 10K  [RESCAV80P320X160X70-8N]  (hidden comment: TC164-JR-0710KL)
RN3  value 47R  [RESCAV80P320X160X70-8N]  (hidden comment: TC164-JR-0747RL)
SJ1  SolderBridge  [JUMP POINT]  (value not drawn)
SJ2  SolderBridge  [JUMP POINT]  (value not drawn)
U2R1  E_PAD  [E_PAD (SMD)]  (value not drawn)
U2T1  E_PAD  [E_PAD (SMD)]  (value not drawn)
U3  TMP75AIDR  [SOIC127P600X175-8N]
U3R  E_PAD  [E_PAD (SMD)]  (value not drawn)
U3T  E_PAD  [E_PAD (SMD)]  (value not drawn)
U4  MK22FN1M0AVLQ12  [QFP50P2200X2200X160-144N]
U4R  E_PAD  [E_PAD (SMD)]  (value not drawn)
U4T  E_PAD  [E_PAD (SMD)]  (value not drawn)
U5  TMP75AIDR  [SOIC127P600X175-8N]
U7  ?  [SOIC127P600X175-8N]
U8  XB3-24Z8UM-J  [XCVR_XB3-24Z8UM-J]
U9  DRV8703QRHBTQ1  [QFN50P500X500X100-33N]
U10  DRV8703QRHBTQ1  [QFN50P500X500X100-33N]
U11  DRV8703QRHBTQ1  [QFN50P500X500X100-33N]
U12  JMTK50N06A  [TO-252AA(DPAK229P990X238-3N)]  (value not drawn)
U13  JMTK50N06A  [TO-252AA(DPAK229P990X238-3N)]  (value not drawn)
U14  JMTK50N06A  [TO-252AA(DPAK229P990X238-3N)]  (value not drawn)
U15  JMTK50N06A  [TO-252AA(DPAK229P990X238-3N)]  (value not drawn)
U16  JMTK50N06A  [TO-252AA(DPAK229P990X238-3N)]  (value not drawn)
U17  JMTK50N06A  [TO-252AA(DPAK229P990X238-3N)]  (value not drawn)
U18  JMTK50N06A  [TO-252AA(DPAK229P990X238-3N)]  (value not drawn)
U19  JMTK50N06A  [TO-252AA(DPAK229P990X238-3N)]  (value not drawn)
U20  JMTK50N06A  [TO-252AA(DPAK229P990X238-3N)]  (value not drawn)
U21  JMTK50N06A  [TO-252AA(DPAK229P990X238-3N)]  (value not drawn)
U22  JMTK50N06A  [TO-252AA(DPAK229P990X238-3N)]  (value not drawn)
U23  JMTK50N06A  [TO-252AA(DPAK229P990X238-3N)]  (value not drawn)
U27  TPS560430XFDBVT  [SOT23-6L]
U29  LTC4015EUHF#PBF  [QFN50P700X500X80-39N]
U33  TPS560430XFDBVT  [SOT23-6L]
U35  TL431ACDBZR  [SOT-23-3(TO-236)]  (value not drawn)
UART3_EXP  68001-108HLF  [HDR1X8 (male)]  (value not drawn)
UART4_EXP  68001-108HLF  [HDR1X8 (male)]  (value not drawn)
V_BRIDGE  E_PAD  [E_PAD (SMD)]  (value not drawn)
V_BUT  E_PAD  [E_PAD (SMD)]  (value not drawn)
Y1  ABM3B-8.000MHZ-B2-T  [OSC_ABM3B-8.000MHZ-B2-T]  (value not drawn)
Y2  value 32.768KHz  [2-SMD (3.2 X 1.5mm)]  (hidden comment: ABS07-32.768KHZ-T)

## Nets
+3V3: 3V3_IN.1 C7.2 C13.2 C14.2 C15.2 C16.2 C17.2 C18.2 C19.2 C23.2 C25.2 C27.2 C28.2 C29.2 C35.2 C40.2 C43.2 C86.2 C105.2 C108.2 C150.2 C155.2 D3.2 D4.2 D5.2 D6.2 D15.2 D16.2 D17.2 D18.2 D19.2 D20.2 D21.2 D22.2 D31.2 D33.2 D35.2 D37.2 J9.01 J28.4(VDD) JP1.1 JP2.1 JP4.1 L1.2 L4.1 L5.1 L12.1 L17.2 Q1.2 R5.2 R6.2 R7.2 R8.2 R9.2 R10.2 R11.2 R12.2 R16.2 R17.2 R18.2 R19.2 R20.2 R21.2 R22.2 R23.2 R24.2 R25.2 R26.1 R27.2 R31.2 R32.2 R33.2 R34.2 R35.2 R36.2 R37.1 R39.2 R40.2 R41.2 R42.1 R43.1 R65.2 R73.2 R84.2 R97.2 R128.2 RN2.5 RN2.6 RN2.7 RN2.8 U3.8(V+) U4.5(VDD) U4.16(VDD) U4.43(VDD) U4.56(VDD) U4.70(VDD) U4.94(VDD) U4.108(VDD) U4.122(VDD) U4.135(VDD) U5.8(V+) U7.8(V+) U29.3(DVCC)
+5V: 5V_IN.1 BUZ.1 C33.2 C61.2 C63.2 C101.2 C113.2 ENC_1.1 ENC_2.1 IC1.5(VCC+) L6.1 L7.1 L13.1 P2.1 R13.2 R133.2 R138.2 R188.2
+24V: C37.2 C121.2 C122.1 C124.1 C127.1 C128.2 C130.2 C131.2 C132.2 C133.2 C134.2 C135.2 C137.1(+) C146.2 C147.2 C148.2 C149.2 F1.1 F1.2 IC7.5 IC7.6 IC7.7 IC7.8 L2.1 L3.1 P1.1 Q9.1(S) Q9.2(S) Q9.3(S) R124.2 R127.2 R137.2 R139.2 R141.2 U27.5(VIN) U29.31(SYS) U33.5(VIN)
+24V_K1: C38.2 C39.2 C41.2 C42.2 C44.1 C45.1 C46.1 D39.1 D39.3 K1.4(NO) R126.1 R129.2 R145.2 U9.27(VDRAIN) U9.28(VM) U10.27(VDRAIN) U10.28(VM) U11.27(VDRAIN) U11.28(VM)
GND: 3V3_IN.2 C3.1 C4.1 C5.1 C6.1 C7.1 C8.1 C9.1 C10.2(-) C11.1 C12.1 C13.1 C14.1 C15.1 C16.1 C17.1 C18.1 C19.1 C20.1 C21.1 C22.1 C23.1 C24.1 C25.1 C27.1 C28.1 C29.1 C30.1 C33.1 C34.2 C35.1 C37.1 C38.1 C39.1 C40.1 C41.1 C42.1 C43.1 C47.1 C51.1 C52.1 C53.1 C54.1 C55.1 C56.1 C57.1 C58.1 C59.1 C60.2(-) C61.1 C62.2(-) C63.1 C64.2(-) C65.2(-) C66.2(-) C67.2(-) C68.1 C69.1 C70.1 C71.1 C72.1 C73.1 C74.1 C75.1 C76.1 C77.1 C86.1 C101.1 C105.1 C106.1 C107.2 C108.1 C109.1 C110.1 C111.1 C113.1 C120.1 C123.1 C124.2 C125.2 C126.1 C127.2 C128.1 C129.1 C130.1 C131.1 C132.1 C133.1 C134.1 C135.1 C137.2(-) C138.1 C139.1 C140.1 C141.1 C142.1 C143.1 C144.1 C146.1 C147.1 C148.1 C149.1 C150.1 C153.1 C155.1 D2.2 D3.1 D4.1 D5.1 D6.1 D7.3 D8.3 D9.A D10.A D11.A D12.A D13.A D14.A D15.1 D16.1 D17.1 D18.1 D19.1 D20.1 D21.1 D22.1 D23.3 D24.3 D25.3 D26.3 D31.1 D33.1 D35.1 D37.1 D40.2(A) DBG_UART.3 ENC_1.4 ENC_2.4 IC1.2(GND) IC3.1 IC3.2 IC3.3 IC4.1 IC4.2 IC4.3 IC6.5 IC6.6 IC6.7 IC6.8 IC8.1 IC8.2 IC8.3 IC9.5 IC9.6 IC9.7 IC9.8 J9.03 J9.05 J9.09 J28.6(VSS) J28.P1(SHIELD) J28.P2(SHIELD) J28.P3(SHIELD) J28.P4(SHIELD) J28.SWB(B) JP1.6 JP2.5 JP3.1 JP4.4 JP5.1 JP6.1 JP7.1 L19.1 LED5.1(K2) LED7.1(K2) LED8.1(K2) LED9.1(K2) LED10.1(K2) LED13.1(K2) LED14.1(K2) LED15.1(K2) P1.2 P2.2 Q2.2(E) Q3.2(E) Q4.2(E) Q5.2(E) Q6.2(E) Q7.2(E) Q8.2(E) Q10.2(E) Q13.2(C) Q15.2(C) Q16.2(C) Q17.2(C) R4.2 R15.1 R38.2 R45.2 R46.2 R47.2 R52.2 R53.2 R54.2 R55.1 R59.1 R61.1 R63.1 R64.1 R81.1 R82.1 R85.1 R88.1 R100.1 R102.1 R105.1 R108.1 R110.2 R112.2 R114.2 R116.2 R117.1 R119.2 R121.1 R125.1 R131.2 R134.1 R135.1 R142.1 R143.1 R144.1 R148.1 R149.1 R150.1 R151.1 R152.1 R153.1 R154.1 R155.2 R156.2 R157.1 R158.1 R159.2 R160.2 R161.1 R162.1 R174.1 R176.1 R178.1 R179.2 R?.1 U3.4(GND) U3.5(A2) U3.6(A1) U3.7(A0) U4.6(VSS) U4.17(VSS) U4.18(VSS) U4.33(VREFL) U4.34(VSSA) U4.44(VSS) U4.57(VSS) U4.71(VSS) U4.93(VSS) U4.107(VSS) U4.121(VSS) U4.134(VSS) U5.4(GND) U5.5(A2) U5.6(A1) U7.4(GND) U8.1(GND) U8.10(GND) U8.12(GND) U8.21(GND) U8.32(GND) U8.34(GND) U9.1(GND) U9.13(GND) U9.17(GND) U9.22(SN) U9.33(EXP) U10.1(GND) U10.13(GND) U10.17(GND) U10.22(SN) U10.33(EXP) U11.1(GND) U11.13(GND) U11.17(GND) U11.22(SN) U11.33(EXP) U27.2(GND) U29.7(SGND) U29.13(EQ) U29.14(GND) U29.39(EXP) U33.2(GND) U35.3(ANODE) UART3_EXP.8 UART4_EXP.8 Y1.2(GND) Y1.4(GND)
K1_1: D36.2(A) K1.1(-_1) Q10.3(C)
K1_2: D38.2(A) K1.2(-_2) Q8.3(C)
K1_5: C138.2 D36.1(C) D38.1(C) K1.5(+) R138.1
PWR1+: D9.K J16.1(P1) J16.2(P1) U9.19(SH1) U14.4(D) U15.3(S)
PWR1-: D12.K J15.1(P1) J15.2(P1) U9.25(SH2) U12.3(S) U13.4(D)
PWR2+: D10.K J18.1(P1) J18.2(P1) U10.19(SH1) U18.4(D) U19.3(S)
PWR2-: D13.K J17.1(P1) J17.2(P1) U10.25(SH2) U16.3(S) U17.4(D)
PWR3+: U11.19(SH1)
PWR3-: U11.25(SH2)
S1_GND: R55.2 U9.21(SP) U9.23(SL2) U13.3(S) U14.3(S)
S2_GND: R59.2 U10.21(SP) U10.23(SL2) U17.3(S) U18.3(S)
S3_GND: U11.21(SP) U11.23(SL2)
V_BRIDGE: C60.1(+) C62.1(+) C64.1(+) C65.1(+) C66.1(+) C67.1(+) C139.2 C140.2 C141.2 C142.2 C143.2 C144.2 D39.4 J27.1(P1) J27.2(P1) Q14.2(E) U12.4(D) U15.4(D) U16.4(D) U19.4(D) U20.4(D) U23.4(D) V_BRIDGE.1
V_BUT: U29.18(BATSENS) V_BUT.1
VCC: C123.2 C125.1 D30.2(A) R107.1 R109.1 R111.1 R113.1 R115.1 R118.1 U29.27(DRVCC) U29.28(INTVCC)
VIN: C106.2 C109.2 C110.2 F2.3 F2.4 IC5.1 IC5.2 IC5.3 R99.2 R103.2 U29.35(VIN)
VIN_DC: D34.4 F2.1 F2.2 J24.1(P1) J24.2(P1) R146.2 R175.2
A0: R7.1 U5.7(A0) ; off-sheet A0
BUZ: Q6.1(B) U4.84(PTB3) ; off-sheet BUZ
CELLS0: R113.2 R114.1 U29.38(CELLS0) ; off-sheet CELLS0
CELLS1: R115.2 R116.1 U29.1(CELLS1) ; off-sheet CELLS1
CELLS2: R118.2 R119.1 U29.2(CELLS2) ; off-sheet CELLS2
CHEM0: R109.2 R110.1 U29.36(CHEM0) ; off-sheet CHEM0
CHEM1: R111.2 R112.1 U29.37(CHEM1) ; off-sheet CHEM1
CLK: J9.04 JP2.3 R15.2 U4.50(PTA0) ; off-sheet CLK
CLN: C115.2 C121.1 R127.1 U29.32(CLN) ; off-sheet CLN
CLP: C115.1 R122.1 U29.33(CLP) ; off-sheet CLP
CS1: RN2.3 U4.104(PTC1/LLWU_P6) U9.5(NSCS) ; off-sheet CS1
CS2: RN2.2 U4.105(PTC2) U10.5(NSCS) ; off-sheet CS2
CS3: RN2.1 U4.106(PTC3/LLWU_P7) U11.5(NSCS) ; off-sheet CS3
CSN: C118.2 C126.2 C129.2 J8.1(P1) J8.2(P1) R96.2 R130.2 U29.19(CSN) ; off-sheet CSN
CSP: C117.1 C118.1 L10.1 Q9.5(D) Q9.6(D) Q9.7(D) Q9.8(D) Q9.9(D) R130.1 U29.20(CSP) ; off-sheet CSP
CTS: RN1.4 U8.24(~{CTS!/DIO7}) ; off-sheet CTS
DATAIN: J28.3(CMD) RN3.3 ; off-sheet DATAIN
DATAOUT: J28.7(DAT0) RN3.1 ; off-sheet DATAOUT
DIO: J9.02 JP2.2 R16.1 U4.53(PTA3) ; off-sheet DIO
ENC11: C56.2 R48.1 U4.60(PTA8) ; off-sheet ENC11
ENC12: C57.2 R49.1 U4.61(PTA9) ; off-sheet ENC12
ENC21: C58.2 R50.1 U4.62(PTA10) ; off-sheet ENC21
ENC22: C59.2 R51.1 U4.63(PTA11) ; off-sheet ENC22
EXP0: C70.2 R58.2 U4.126(PTC19) ; off-sheet EXP0
EXP1: C71.2 R66.2 U4.125(PTC18) ; off-sheet EXP1
EXP2: C72.2 R67.2 U4.75(PTA24) ; off-sheet EXP2
EXP3: C73.2 R68.2 U4.76(PTA25) ; off-sheet EXP3
EXP4: C74.2 R69.2 U4.77(PTA26) ; off-sheet EXP4
EXP5: C75.2 R70.2 U4.78(PTA27) ; off-sheet EXP5
EXP6: C76.2 R71#2.2 U4.79(PTA28) ; off-sheet EXP6
EXP7: C77.2 R72.2 U4.80(PTA29) ; off-sheet EXP7
GH11: U9.18(GH1) U15.1(G) ; off-sheet GH11
GH12: U9.26(GH2) U12.1(G) ; off-sheet GH12
GH21: U10.18(GH1) U19.1(G) ; off-sheet GH21
GH22: U10.26(GH2) U16.1(G) ; off-sheet GH22
GH31: U11.18(GH1) U23.1(G) ; off-sheet GH31
GH32: U11.26(GH2) U20.1(G) ; off-sheet GH32
GL11: U9.20(GL1) U14.1(G) ; off-sheet GL11
GL12: U9.24(GL2) U13.1(G) ; off-sheet GL12
GL21: U10.20(GL1) U18.1(G) ; off-sheet GL21
GL22: U10.24(GL2) U17.1(G) ; off-sheet GL22
GL31: U11.20(GL1) U22.1(G) ; off-sheet GL31
GL32: U11.24(GL2) U21.1(G) ; off-sheet GL32
GP1: U4.67(PTA15) U8.31(AD0/DIO0) ; off-sheet GP1
GP2: U4.68(PTA16) U8.30(AD1/DIO1) ; off-sheet GP2
GPIO0: D23.1 GPIO_EXP.1 R57.1 R64.2 ; off-sheet GPIO0
GPIO1: D23.2 GPIO_EXP.2 R71#1.1 R148.2 ; off-sheet GPIO1
GPIO2: D24.1 GPIO_EXP.3 R75.1 R154.2 ; off-sheet GPIO2
GPIO3: D24.2 GPIO_EXP.4 R76.1 R153.2 ; off-sheet GPIO3
GPIO4: D25.1 GPIO_EXP.5 R77.1 R152.2 ; off-sheet GPIO4
GPIO5: D25.2 GPIO_EXP.6 R78.1 R151.2 ; off-sheet GPIO5
GPIO6: D26.1 GPIO_EXP.7 R79.1 R150.2 ; off-sheet GPIO6
GPIO7: D26.2 GPIO_EXP.8 R80.1 R149.2 ; off-sheet GPIO7
INFET: IC5.4 U29.34(INFET) ; off-sheet INFET
JP1_CTS: JP1.4 L19.2 R167.2 ; off-sheet JP1_CTS
JP1_RTS: JP1.5 R169.2 ; off-sheet JP1_RTS
JP1_RX: JP1.3 R165.2 ; off-sheet JP1_RX
JP1_TX: JP1.2 R163.2 ; off-sheet JP1_TX
K1_RESET: R135.2 R136.2 U4.92(PTB11) ; off-sheet K1_RESET
K1_SET: R131.1 R132.2 U4.91(PTB10) ; off-sheet K1_SET
LED1: Q2.1(B) U4.95(PTB16) ; off-sheet LED1
LED2: Q3.1(B) U4.96(PTB17) ; off-sheet LED2
LED3: Q4.1(B) U4.99(PTB20) ; off-sheet LED3
LED4: Q5.1(B) U4.100(PTB21) ; off-sheet LED4
LED13: R28.2 U8.7(RSSI_PWM/DIO10) ; off-sheet LED13
LED14: R30.2 U8.9(~{DTR!/SLEEP_RQ/DIO8}) ; off-sheet LED14
LED15: R83.2 U8.26(ASSOCIATE/DIO5) ; off-sheet LED15
M_RX1: RN1.2 SJ2.3 U2R1.1 ; off-sheet M_RX1
M_TX1: RN1.1 SJ1.3 U2T1.1 ; off-sheet M_TX1
MISO: R39.1 R40.1 R41.1 R73.1 RN3.5 U4.112(PTC7) U7.2(SCL) U9.4(SDO) U10.4(SDO) U11.4(SDO) ; off-sheet MISO
MODE1: R42.2 R46.1 U9.11(MODE) ; off-sheet MODE1
MODE2: R43.2 R47.1 U10.11(MODE) ; off-sheet MODE2
MODE3: R37.2 R45.1 U11.11(MODE) ; off-sheet MODE3
MOSI: RN3.7 U4.111(PTC6/LLWU_P10) U7.5(A2) U9.6(SDI) U10.6(SDI) U11.6(SDI) ; off-sheet MOSI
MPPT: R107.2 R108.2 U29.21(MPPT) ; off-sheet MPPT
NFAULT1: R17.1 U4.87(PTB6) U9.10(NFAULT) ; off-sheet NFAULT1
NFAULT2: R19.1 U4.86(PTB5) U10.10(NFAULT) ; off-sheet NFAULT2
NFAULT3: R21.1 U4.85(PTB4) U11.10(NFAULT) ; off-sheet NFAULT3
NTC: J22.1(P1) J22.2(P1) R123.1 R125.2 U29.11(NTC) ; off-sheet NTC
NWDFLT1: R22.1 U4.90(PTB9) U9.9(NWDFLT) ; off-sheet NWDFLT1
NWDFLT2: R20.1 U4.89(PTB8) U10.9(NWDFLT) ; off-sheet NWDFLT2
NWDFLT3: R18.1 U4.88(PTB7) U11.9(NWDFLT) ; off-sheet NWDFLT3
PW11: PW11.1 U4.14(PTE11) U9.2(IN1/PH) ; off-sheet PW11
PW12: PW12.1 U4.15(PTE12) U9.3(IN2/EN) ; off-sheet PW12
PW21: PW21.1 U4.136(PTD7) U10.2(IN1/PH) ; off-sheet PW21
PW22: PW22.1 U4.133(PTD6/LLWU_P15) U10.3(IN2/EN) ; off-sheet PW22
PW31: PW31.1 U4.97(PTB18) U11.2(IN1/PH) ; off-sheet PW31
PW32: PW32.1 U4.98(PTB19) U11.3(IN2/EN) ; off-sheet PW32
RST: C30.2 J9.10 JP2.4 R27.1 U4.74(~{RESET_B}) ; off-sheet RST
RTS: RN1.3 U8.27(~{RTS!/DIO6}) ; off-sheet RTS
RX1: JP4.3 SJ2.1 ; off-sheet RX1
SCL: R35.1 U4.115(PTC10) U29.4(SCL) ; off-sheet SCL
SCLK: RN3.6 U4.110(PTC5/LLWU_P9) U7.6(A1) U9.7(SCLK) U10.7(SCLK) U11.7(SCLK) ; off-sheet SCLK
SD_CLK: J28.5(CLK) RN3.2 ; off-sheet SD_CLK
SD_CS: RN3.8 U4.109(PTC4/LLWU_P8) ; off-sheet SD_CS
SD_SWA: J28.SWA(A) R65.1 U4.83(PTB2) ; off-sheet SD_SWA
SDA: R34.1 U4.116(PTC11/LLWU_P11) U29.5(SDA) ; off-sheet SDA
SEL: J28.2(CD/DAT3) R128.1 RN3.4 ; off-sheet SEL
SLEEP1: R31.1 U4.144(PTD15) U9.8(NSLEEP) ; off-sheet SLEEP1
SLEEP2: R32.1 U4.143(PTD14) U10.8(NSLEEP) ; off-sheet SLEEP2
SLEEP3: R33.1 U4.142(PTD13) U11.8(NSLEEP) ; off-sheet SLEEP3
SMBALERT: R36.1 U4.114(PTC9) U29.6(~{SMBALERT}) ; off-sheet SMBALERT
SO1: C4.2 U4.28(ADC0_DM0/ADC1_DM3) U9.16(SO) ; off-sheet SO1
SO2: C5.2 U4.29(ADC1_DP0/ADC0_DP3) U10.16(SO) ; off-sheet SO2
SO3: C6.2 U4.30(ADC1_DM0/ADC0_DM3) U11.16(SO) ; off-sheet SO3
TMP_SCL: R24.1 U3.2(SCL) U4.81(PTB0/LLWU_P5) U5.2(SCL) ; off-sheet TMP_SCL
TMP_SDA: R23.1 U3.1(SDA) U4.82(PTB1) U5.1(SDA) ; off-sheet TMP_SDA
TX1: JP4.2 SJ1.1 ; off-sheet TX1
U3_ALERT: R12.1 U3.3(ALERT) U4.45(PTE24) ; off-sheet U3_ALERT
U4_CTS: RN1.8 U4.127(PTD0/LLWU_P12) ; off-sheet U4_CTS
U4_RTS: RN1.7 U4.128(PTD1) ; off-sheet U4_RTS
U4_RX1: RN1.6 U4.129(PTD2/LLWU_P13) ; off-sheet U4_RX1
U4_TX1: RN1.5 U4.130(PTD3) ; off-sheet U4_TX1
U5_ALERT: R11.1 U4.46(PTE25) U5.3(ALERT) ; off-sheet U5_ALERT
U7_CS: RN2.4 U4.103(PTC0) U7.1(SDA) ; off-sheet U7_CS
U8_RST: U4.69(PTA17) U8.6(~{RESET}) ; off-sheet U8_RST
U9_AVDD: C47.2 R56.1 U9.14(AVDD) ; off-sheet U9_AVDD
U9_VREF: R52.1 R56.2 U9.15(VREF) ; off-sheet U9_VREF
U10_AVDD: C51.2 R60.1 U10.14(AVDD) ; off-sheet U10_AVDD
U10_VREF: R53.1 R60.2 U10.15(VREF) ; off-sheet U10_VREF
U11_AVDD: C52.2 R62.1 U11.14(AVDD) ; off-sheet U11_AVDD
U11_VREF: R54.1 R62.2 U11.15(VREF) ; off-sheet U11_VREF
UART1_RX: DBG_UART.2 U4.2(PTE1/LLWU_P0) ; off-sheet UART1_RX
UART1_TX: DBG_UART.1 U4.1(PTE0) ; off-sheet UART1_TX
UART3_CTS: U4.9(PTE6) UART3_EXP.4 ; off-sheet UART3_CTS
UART3_RTS: U4.10(PTE7) UART3_EXP.5 ; off-sheet UART3_RTS
UART3_RX: U3R.1 U4.8(PTE5) UART3_EXP.3 ; off-sheet UART3_RX
UART3_RX1: U4.123(PTC16) UART4_EXP.7 ; off-sheet UART3_RX1
UART3_TX: U3T.1 U4.7(PTE4/LLWU_P2) UART3_EXP.2 ; off-sheet UART3_TX
UART3_TX1: U4.124(PTC17) UART4_EXP.6 ; off-sheet UART3_TX1
UART4_CTS: U4.118(PTC13) UART4_EXP.4 ; off-sheet UART4_CTS
UART4_RTS: U4.117(PTC12) UART4_EXP.5 ; off-sheet UART4_RTS
UART4_RX: U4.119(PTC14) U4R.1 UART4_EXP.3 ; off-sheet UART4_RX
UART4_TX: U4.120(PTC15) U4T.1 UART4_EXP.2 ; off-sheet UART4_TX
UART5_CTS1: R168.1 U4.140(PTD11) ; off-sheet UART5_CTS1
UART5_RTS1: R170.1 U4.139(PTD10) ; off-sheet UART5_RTS1
UART5_RX: U4.12(PTE9) UART3_EXP.7 ; off-sheet UART5_RX
UART5_RX1: R166.1 U4.137(PTD8) ; off-sheet UART5_RX1
UART5_TX: U4.11(PTE8) UART3_EXP.6 ; off-sheet UART5_TX
UART5_TX1: R164.1 U4.138(PTD9) ; off-sheet UART5_TX1
USB_DM: U4.20(USB0_DM) ; off-sheet USB_DM
USB_DP: U4.19(USB0_DP) ; off-sheet USB_DP
VBAT: C10.1(+) D2.3 U4.42(VBAT) ; off-sheet VBAT
VDDA: C8.2 C9.2 D2.1 L1.1 U4.31(VDDA) ; off-sheet VDDA
Net5V_IN_2: 5V_IN.2 Q7.3(C)
NetBUZ_2: BUZ.2 Q6.3(C)
NetC3_2: C3.2 Q1.1 R4.1 U4.26(ADC1_DM1)
NetC11_2: C11.2 U4.32(VREFH) U4.37(VREF_OUT/CMP1_IN5/CMP0_IN5/ADC1_SE18)
NetC12_2: C12.2 U4.21(VOUT33) U4.22(VREGIN)
NetC20_2: C20.2 U4.72(PTA18) Y1.1
NetC21_2: C21.2 U4.40(XTAL32) Y2.2
NetC22_2: C22.2 U4.41(EXTAL32) Y2.1
NetC24_2: C24.2 U4.73(PTA19) Y1.3
NetC34_1: C34.1 L17.1 U8.2(VCC)
NetC44_2: C44.2 U9.29(VCP)
NetC45_2: C45.2 U10.29(VCP)
NetC46_2: C46.2 U11.29(VCP)
NetC48_1: C48.1 U9.30(CPH)
NetC48_2: C48.2 U9.31(CPL)
NetC49_1: C49.1 U10.30(CPH)
NetC49_2: C49.2 U10.31(CPL)
NetC50_1: C50.1 U11.30(CPH)
NetC50_2: C50.2 U11.31(CPL)
NetC53_2: C53.2 U9.12(DVDD)
NetC54_2: C54.2 U10.12(DVDD)
NetC55_2: C55.2 U11.12(DVDD)
NetC68_2: C68.2 L2.2 L4.2 L6.2 UART3_EXP.1
NetC69_2: C69.2 L3.2 L5.2 L7.2 UART4_EXP.1
NetC104_1: C104.1 D29.1(C) IC9.4 R96.1
NetC104_2: C104.2 D29.2(A) IC9.1 IC9.2 IC9.3 J14.1(P1) J14.2(P1)
NetC107_1: C107.1 R106.1 U29.8(UVCLFB)
NetC111_2: C111.2 C112.2 U29.9(VC)
NetC112_1: C112.1 R117.2
NetC114_1: C114.1 R120.1 U29.17(CCREFP)
NetC114_2: C114.2 R120.2
NetC116_1: C116.1 D30.1(C) U29.25(BOOST)
NetC116_2: C116.2 U29.23(SW)
NetC117_2: C117.2 U29.15(CSPM5)
NetC119_1: C119.1 F1.3 F1.4 K1.3(COM)
NetC119_2: C119.2 R126.2
NetC120_2: C120.2 U29.22(2P5VCC)
NetC122_2: C122.2 U29.30(SYSM5)
NetC136_1: C136.1 L13.2 U33.6(SW)
NetC136_2: C136.2 U33.1(CB)
NetC145_1: C145.1 L12.2 U27.6(SW)
NetC145_2: C145.2 U27.1(CB)
NetC153_2: C153.2 R171.2 R175.1 R176.2
NetC154_1: C154.1 D27.1(C) IC6.4 R146.1 R180.1
NetC154_2: C154.2 D27.2(A) D28.A D32.A IC6.1 IC6.2 IC6.3 J10.1(P1) J10.2(P1) J11.1(P1) J11.2(P1) R180.2
NetD3_3: D3.3 Q13.1(E) R48.2 R95.2 R159.1
NetD4_3: D4.3 Q17.1(E) R49.2 R160.1 R183.2
NetD5_3: D5.3 Q15.1(E) R50.2 R156.1 R185.2
NetD6_3: D6.3 Q16.1(E) R51.2 R155.1 R186.2
NetD7_1: D7.1 ENC_1.2 R95.1 R162.2 R181.1
NetD7_2: D7.2 ENC_1.3 R161.2 R182.1 R183.1
NetD8_1: D8.1 ENC_2.2 R157.2 R184.1 R185.1
NetD8_2: D8.2 ENC_2.3 R158.2 R186.1 R187.1
NetD11_K: D11.K J20.1(P1) J20.2(P1) U22.4(D) U23.3(S)
NetD14_K: D14.K J19.1(P1) J19.2(P1) U20.3(S) U21.4(D)
NetD15_3: D15.3 R57.2 R58.1 R63.2
NetD16_3: D16.3 R66.1 R71#1.2 R144.2
NetD17_3: D17.3 R67.1 R75.2 R143.2
NetD18_3: D18.3 R68.1 R76.2 R102.2
NetD19_3: D19.3 R69.1 R77.2 R88.2
NetD20_3: D20.3 R70.1 R78.2 R85.2
NetD21_3: D21.3 R71#2.1 R79.2 R82.2
NetD22_3: D22.3 R72.1 R80.2 R81.2
NetD28_K: D28.K J2.2(P1)
NetD31_3: D31.3 R163.1 R164.2
NetD32_K: D32.K J12.2(P1)
NetD33_3: D33.3 R165.1 R166.2
NetD34_1: D34.1 J2.1(P1)
NetD34_3: D34.3 J12.1(P1)
NetD35_3: D35.3 R167.1 R168.2
NetD37_3: D37.3 R169.1 R170.2
NetD40_1: D40.1(C) IC4.4 R147.2 R179.1
NetIC1_1: IC1.1(1IN+) R171.1 R172.2
NetIC1_3: IC1.3(1IN-) R173.2 R188.1 U35.1(CATHODE)
NetIC1_4: IC1.4(OUT) R172.1 R177.2
NetIC3_4: IC3.4 R177.1 R178.2
NetIC3_5: IC3.5 IC3.6 IC3.7 IC3.8 J23.1(P1) J23.2(P1)
NetIC4_5: IC4.5 IC4.6 IC4.7 IC4.8 J26.1(P1) J26.2(P1)
NetIC5_5: IC5.5 IC5.6 IC5.7 IC5.8 R122.2 R124.1
NetIC7_1: IC7.1 IC7.2 IC7.3 IC8.5 IC8.6 IC8.7 IC8.8 L10.2
NetIC7_4: IC7.4 U29.24(TG)
NetIC8_4: IC8.4 U29.26(BG)
NetLED1_1: LED1.1(K2) Q2.3(C)
NetLED1_2: LED1.2(A2) R5.1
NetLED2_1: LED2.1(K2) Q3.3(C)
NetLED2_2: LED2.2(A2) R6.1
NetLED3_1: LED3.1(K2) Q4.3(C)
NetLED3_2: LED3.2(A2) R8.1
NetLED4_1: LED4.1(K2) Q5.3(C)
NetLED4_2: LED4.2(A2) R10.1
NetLED5_2: LED5.2(A2) R99.1
NetLED7_2: LED7.2(A2) R129.1
NetLED8_2: LED8.2(A2) R137.1
NetLED9_2: LED9.2(A2) R13.1
NetLED10_2: LED10.2(A2) R9.1
NetLED13_2: LED13.2(A2) R28.1
NetLED14_2: LED14.2(A2) R30.1
NetLED15_2: LED15.2(A2) R83.1
NetQ7_1: Q7.1(B) R44.1
NetQ8_1: Q8.1(B) R136.1
NetQ9_4: Q9.4(G) U29.29(OUTFET)
NetQ10_1: Q10.1(B) R132.1
NetQ13_3: Q13.3(B) R181.2
NetQ14_1: Q14.1(B) R145.1
NetQ14_3: Q14.3(C) R147.1
NetQ15_3: Q15.3(B) R184.2
NetQ16_3: Q16.3(B) R187.2
NetQ17_3: Q17.3(B) R182.2
NetR25_1: R25.1 U7.7(A0)
NetR26_2: R26.2 U7.3(ALERT)
NetR38_1: R38.1 R44.2 U4.59(PTA7)
NetR61_2: R61.2 U21.3(S) U22.3(S)
NetR84_1: R84.1 U8.11(SPI_!ATTN!/!BOOTMODE!/DIO19)
NetR97_1: R97.1 R100.2 U27.3(FB)
NetR103_1: R103.1 R104.2
NetR104_1: R104.1 R105.2 R106.2
NetR121_2: R121.2 U29.10(RT)
NetR123_2: R123.2 U29.12(NTCBIAS)
NetR133_1: R133.1 R134.2 U33.3(FB)
NetR139_1: R139.1 R?.2 U33.4(EN)
NetR141_1: R141.1 R142.2 U27.4(EN)
NetR173_1: R173.1 R174.2 U35.2(REF)
NetSJ1_2: SJ1.2 U8.4(DIN/!CONFIG!/DIO14)
NetSJ2_2: SJ2.2 U8.3(DOUT/DIO13)

Not connected (* = marked no-connect by the designer): J9 06* 07* 08*; J28 1(DAT2) 8(DAT1); U4 3(PTE2/LLWU_P1)* 4(PTE3)* 13(PTE10)* 23(ADC0_DP1)* 24(ADC0_DM1)* 25(ADC1_DP1)* 27(ADC0_DP0/ADC1_DP3)* 35(ADC1_SE16/CMP2_IN2/ADC0_SE22)* 36(ADC0_SE16/CMP1_IN2/ADC0_SE21)* 38(DAC0_OUT/CMP1_IN3/ADC0_SE23)* 39(DAC1_OUT/CMP0_IN4/CMP2_IN3/ADC1_SE23)* 47(PTE26)* 48(PTE27)* 49(PTE28)* 51(PTA1)* 52(PTA2)* 54(PTA4/LLWU_P3)* 55(PTA5)* 58(PTA6)* 64(PTA12)* 65(PTA13/LLWU_P4)* 66(PTA14)* 101(PTB22)* 102(PTB23)* 113(PTC8)* 131(PTD4/LLWU_P14)* 132(PTD5)* 141(PTD12)*; U8 5(DIO12)* 8(PWM1/DIO11)* 13(SPI_CLK/DIO18)* 14(SPI_!SSEL!/DIO17)* 15(SPI_MOSI/DIO16)* 16(SPI_MISO/DIO15)* 23(DIO4)* 25(ON/!SLEEP!/DIO9)* 28(AD3/DIO3)* 29(AD2/DIO2)* 33(RF)*; U9 32(NC)*; U10 32(NC)*; U11 32(NC)*; U29 16(CCREFM)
